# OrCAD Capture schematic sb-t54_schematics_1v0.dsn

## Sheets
1 01. Board info: title: SB-T54    01. Board info; note: 8000040000
2 02. CoM Connector: size C; title: SB-T54    02. CARRIER BOARD INTERFACE
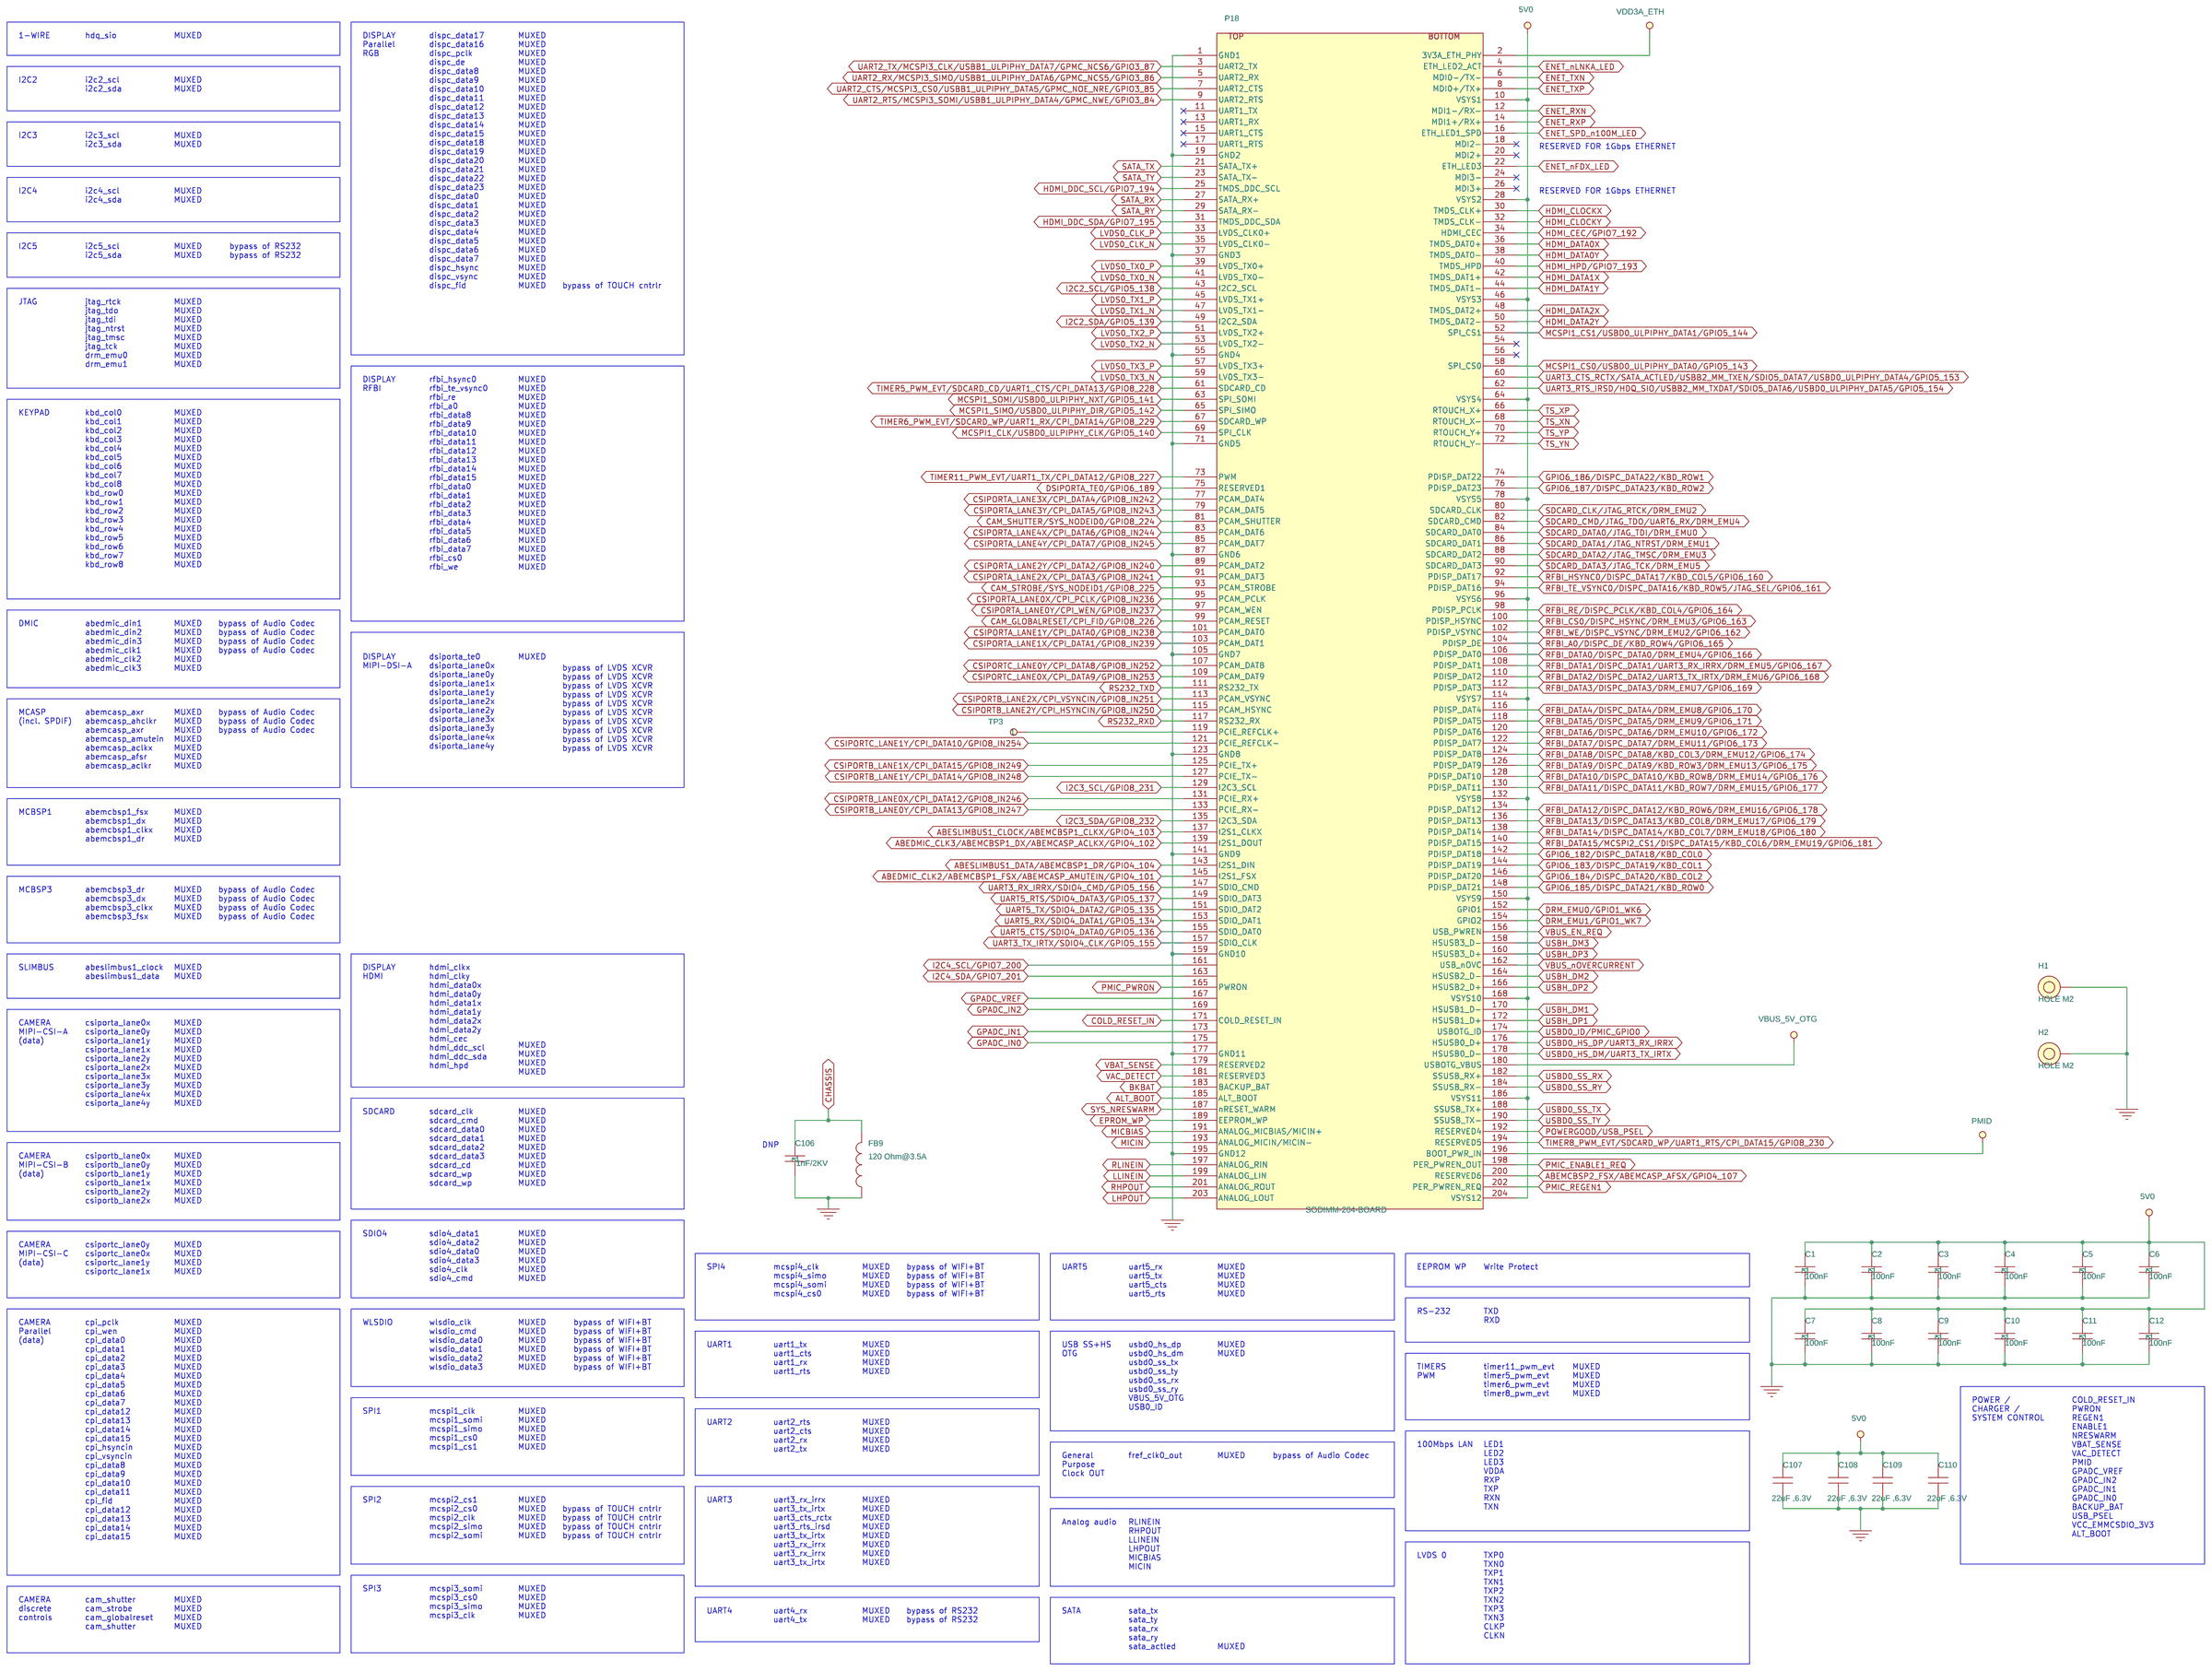
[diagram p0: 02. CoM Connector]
3 03. DVI Transmitter: size B; title: SB-T54  03. DVI Transmitter; rev: 1.0
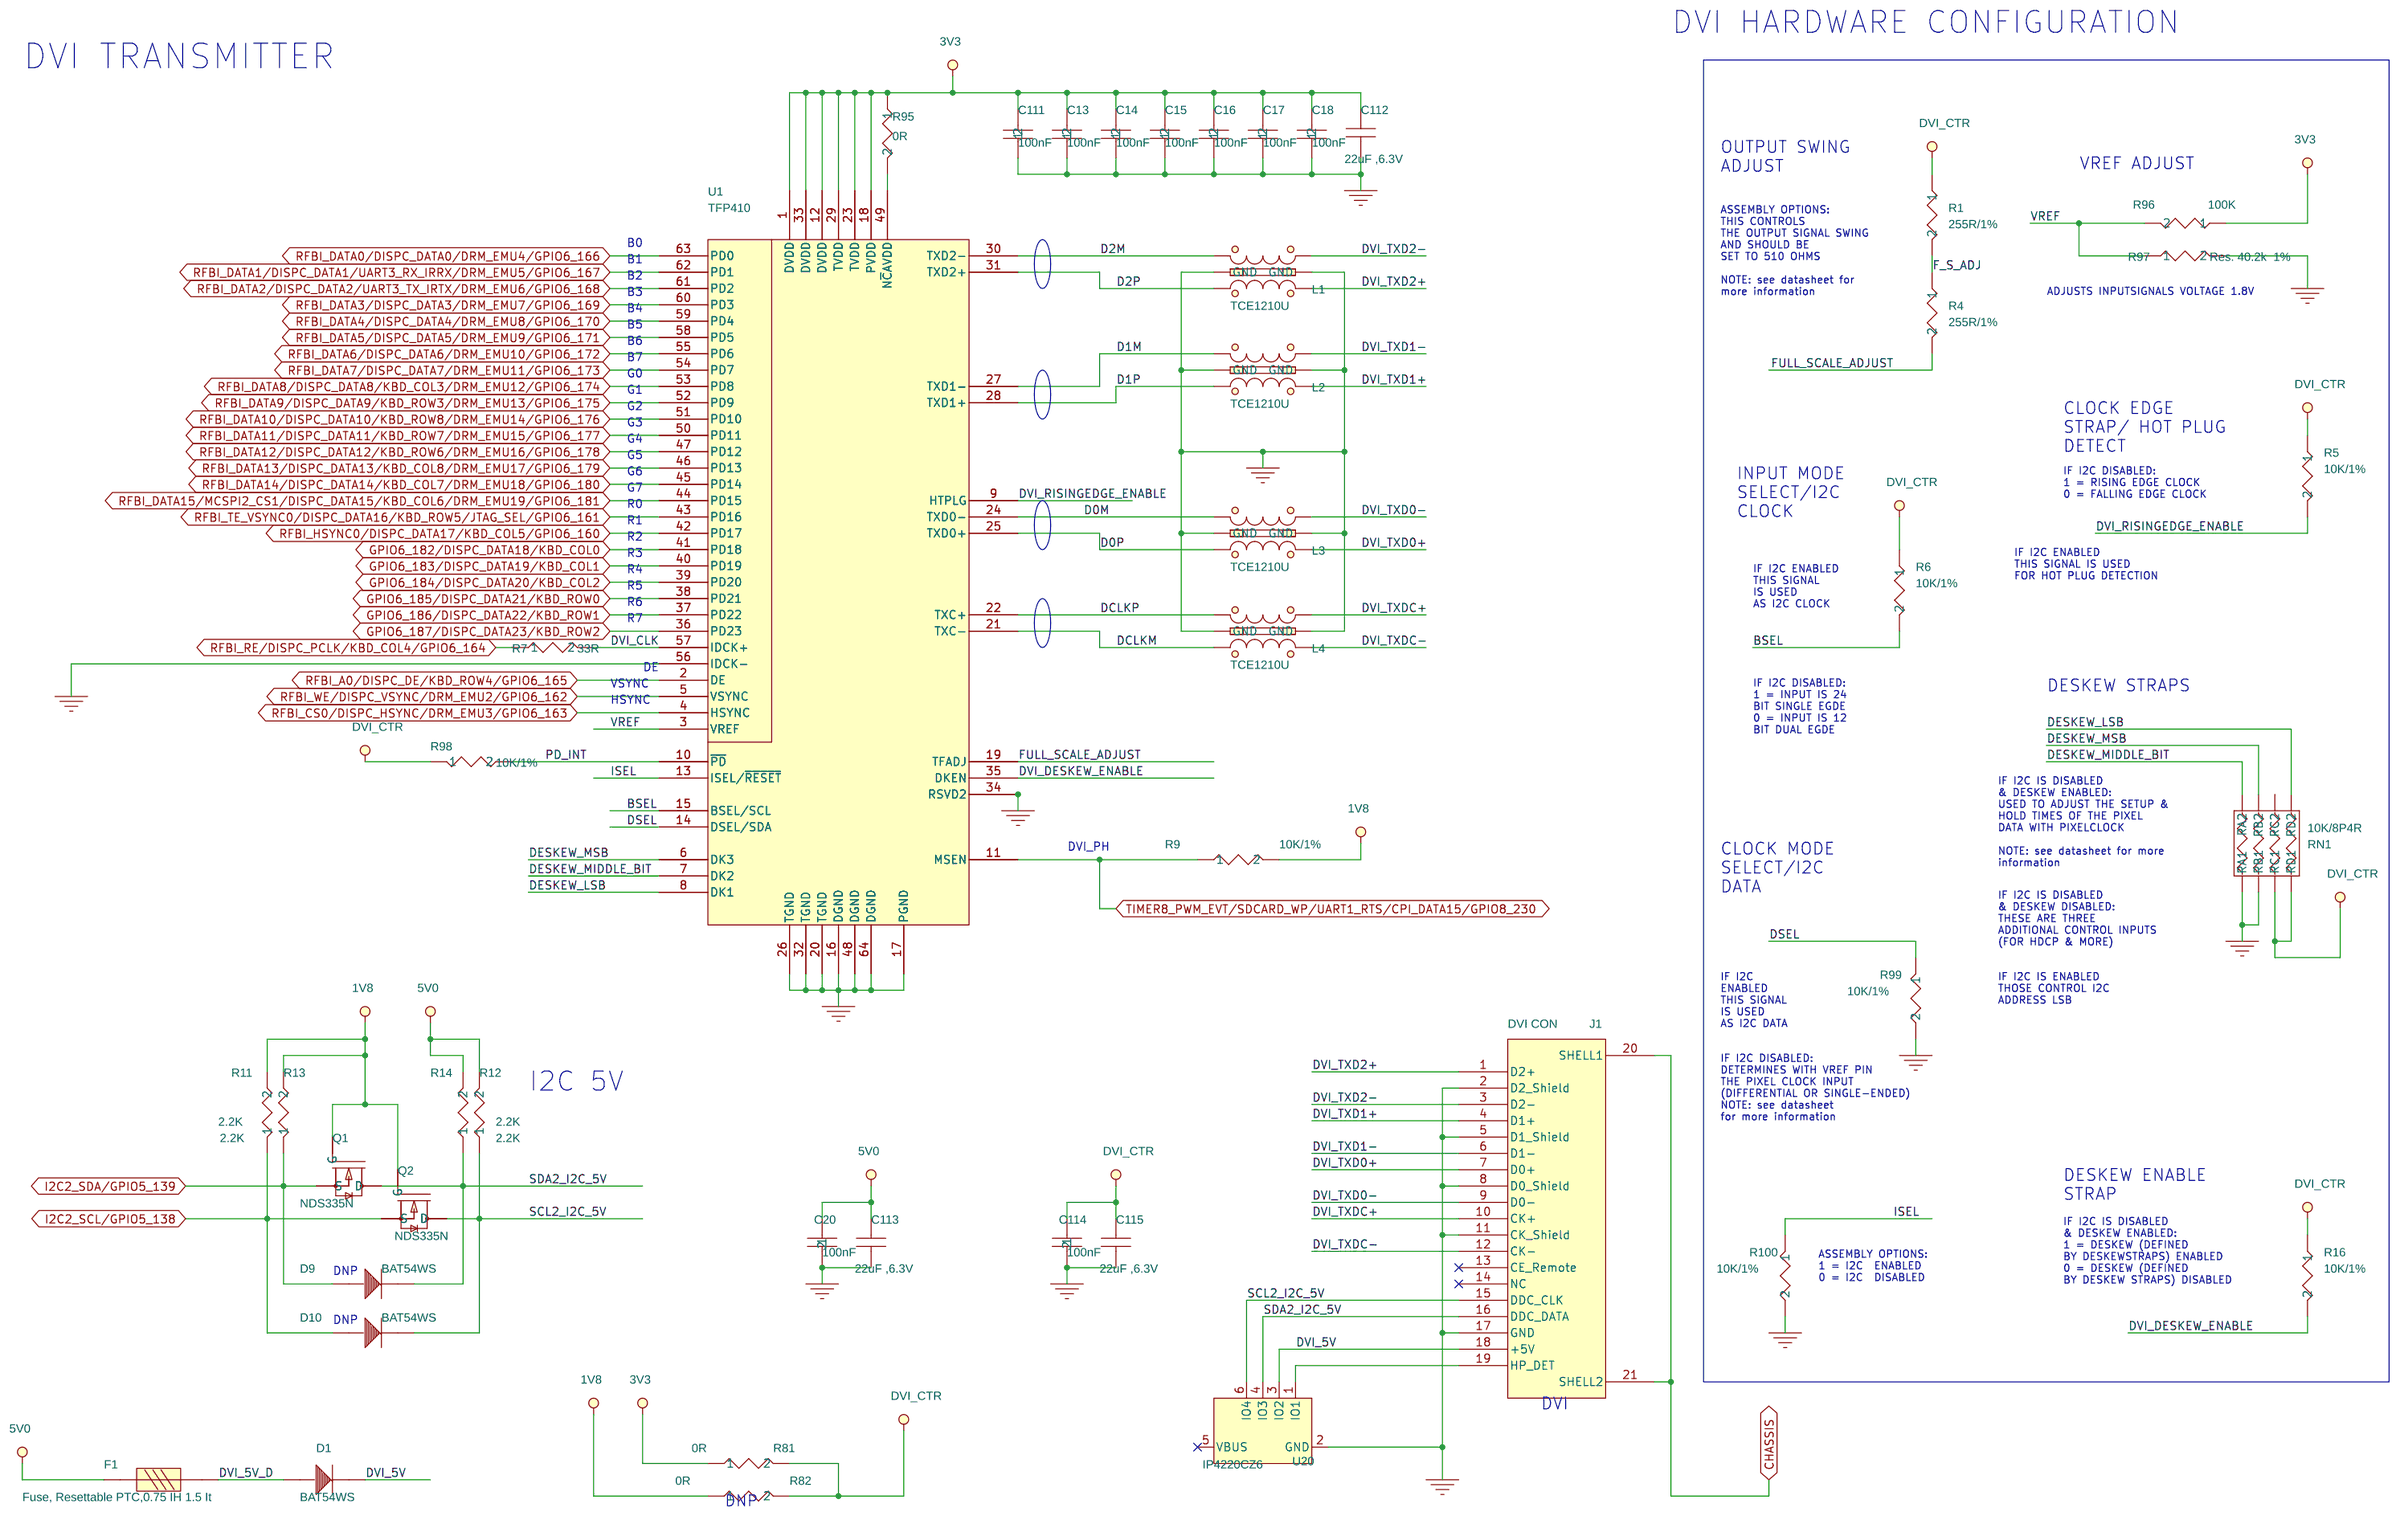
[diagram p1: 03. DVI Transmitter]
4 04. Parallel RGB: size B; title: SB-54  04. Parallel RGB; rev: 1.0
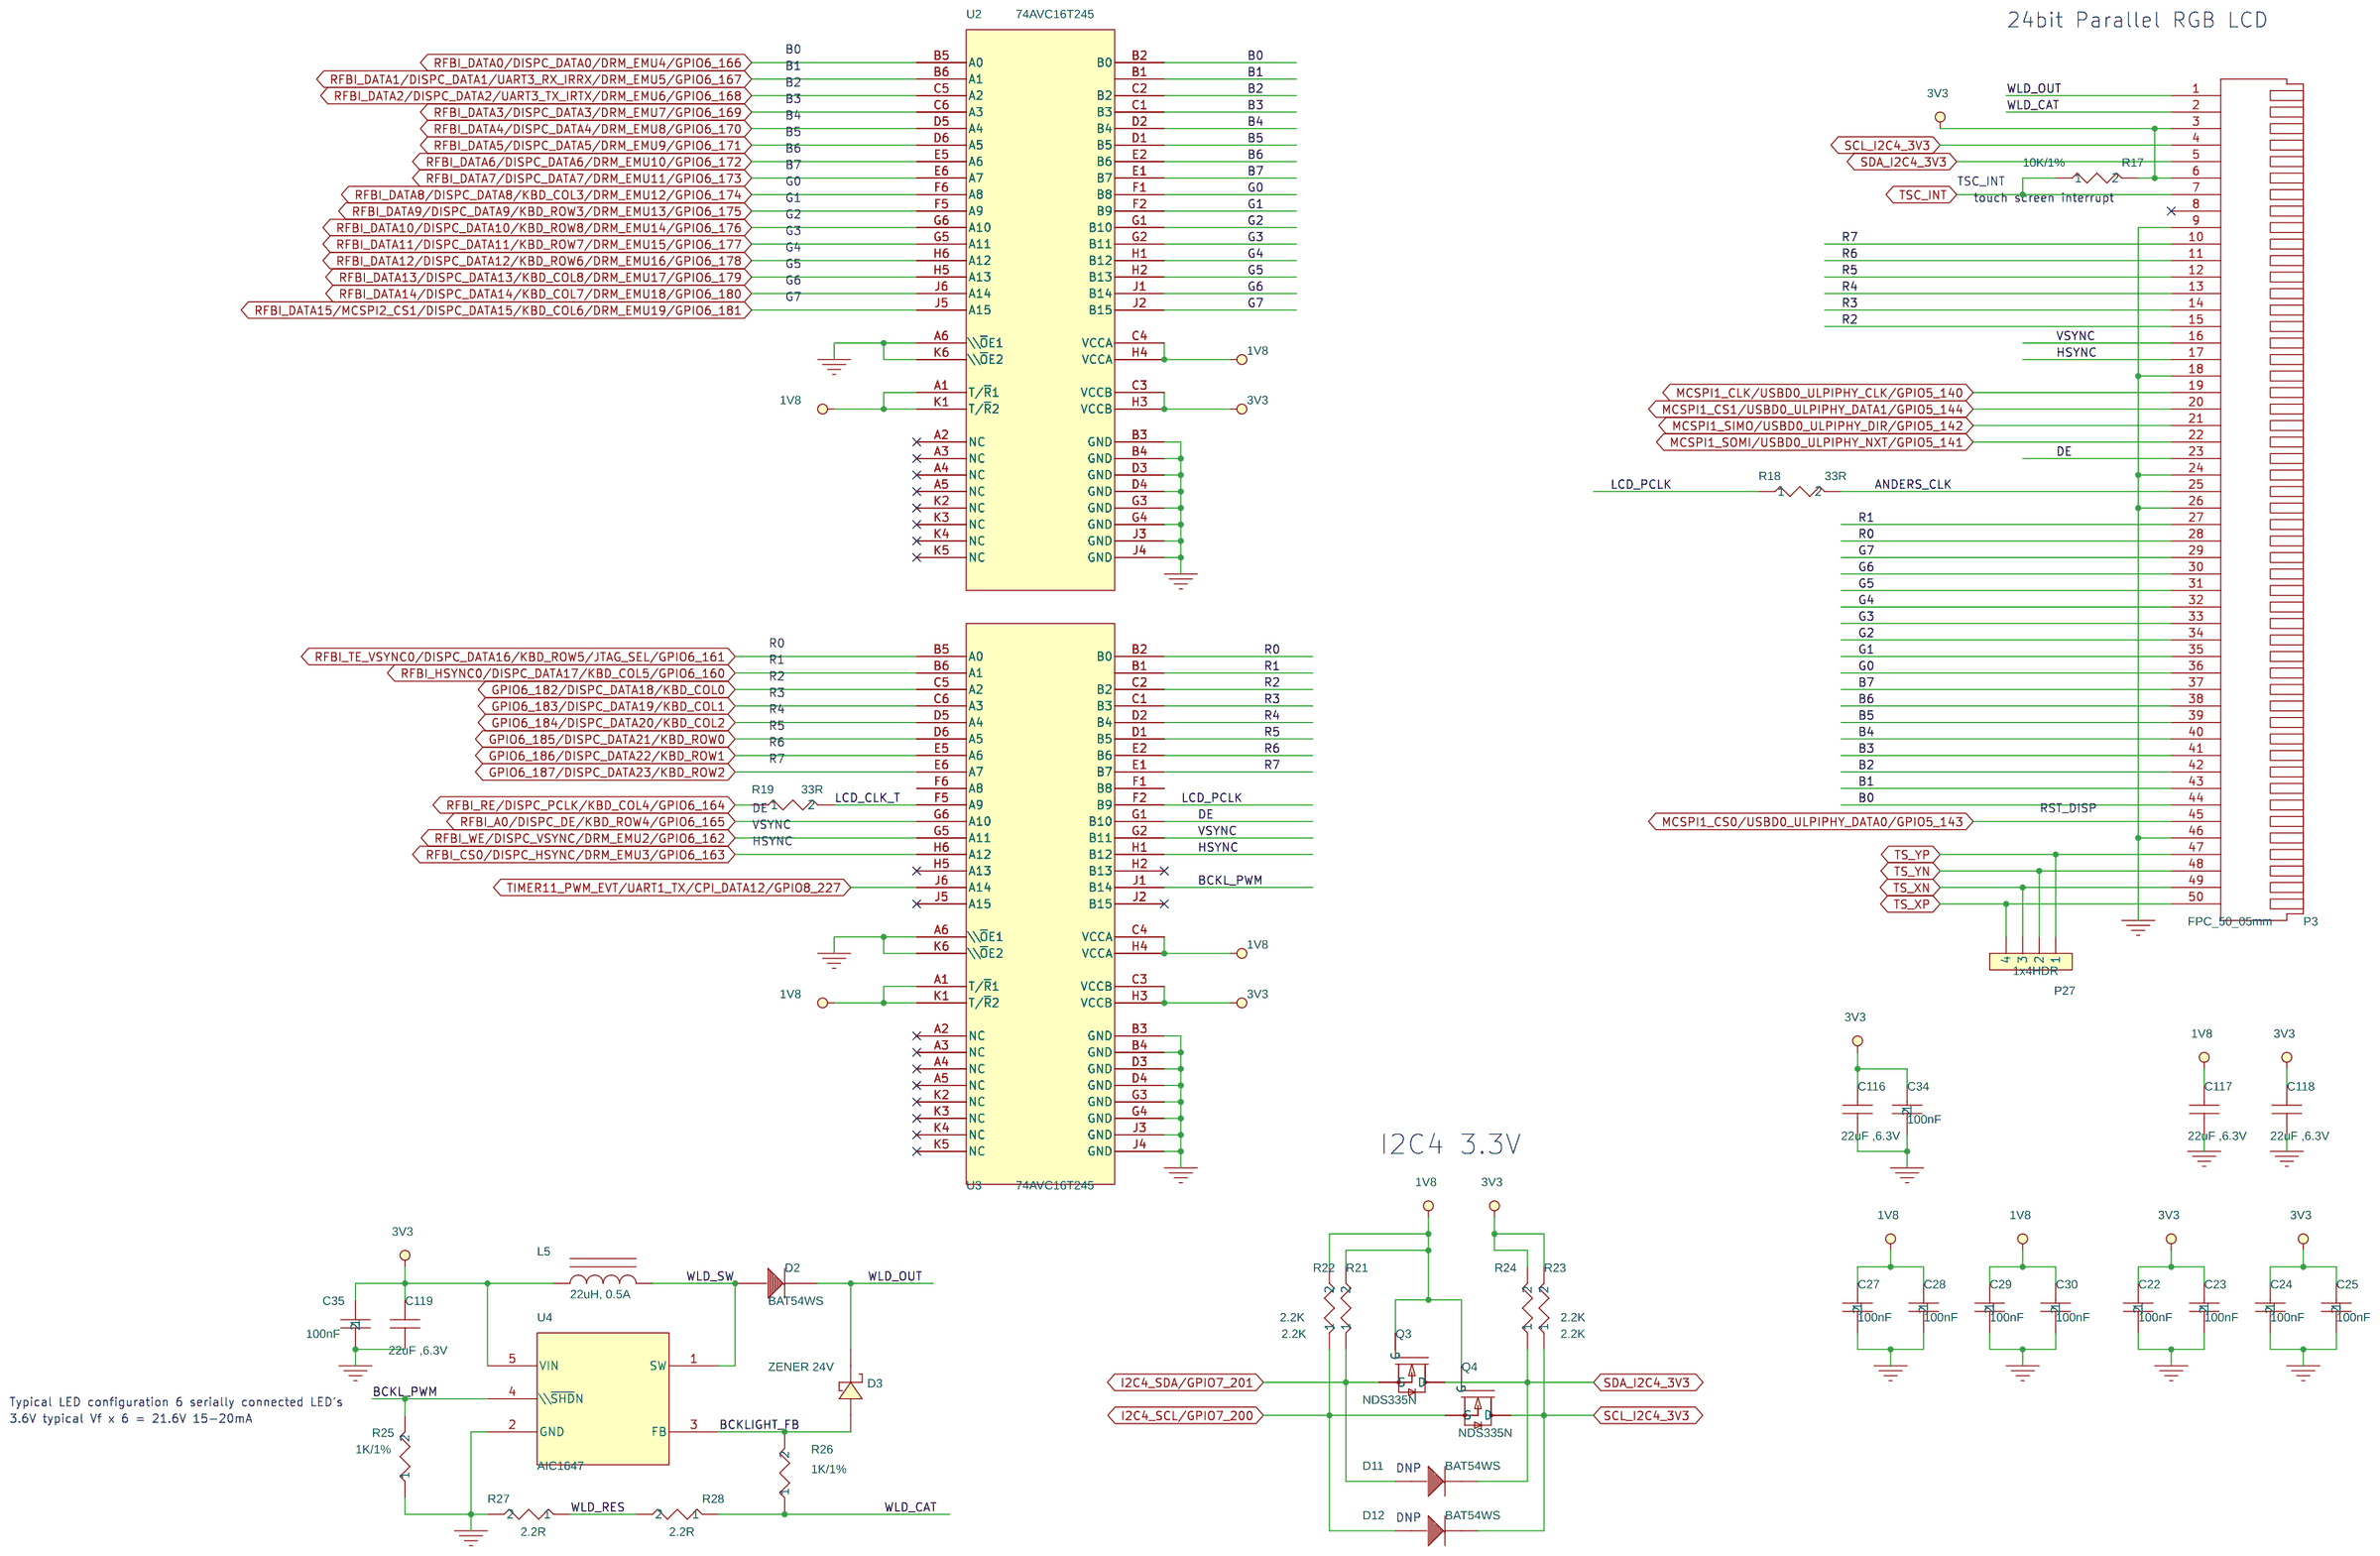
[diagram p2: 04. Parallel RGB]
5 06. MMC & UARTS: size B; title: SB-T54  06. MMC & UARTS; rev: 1.0
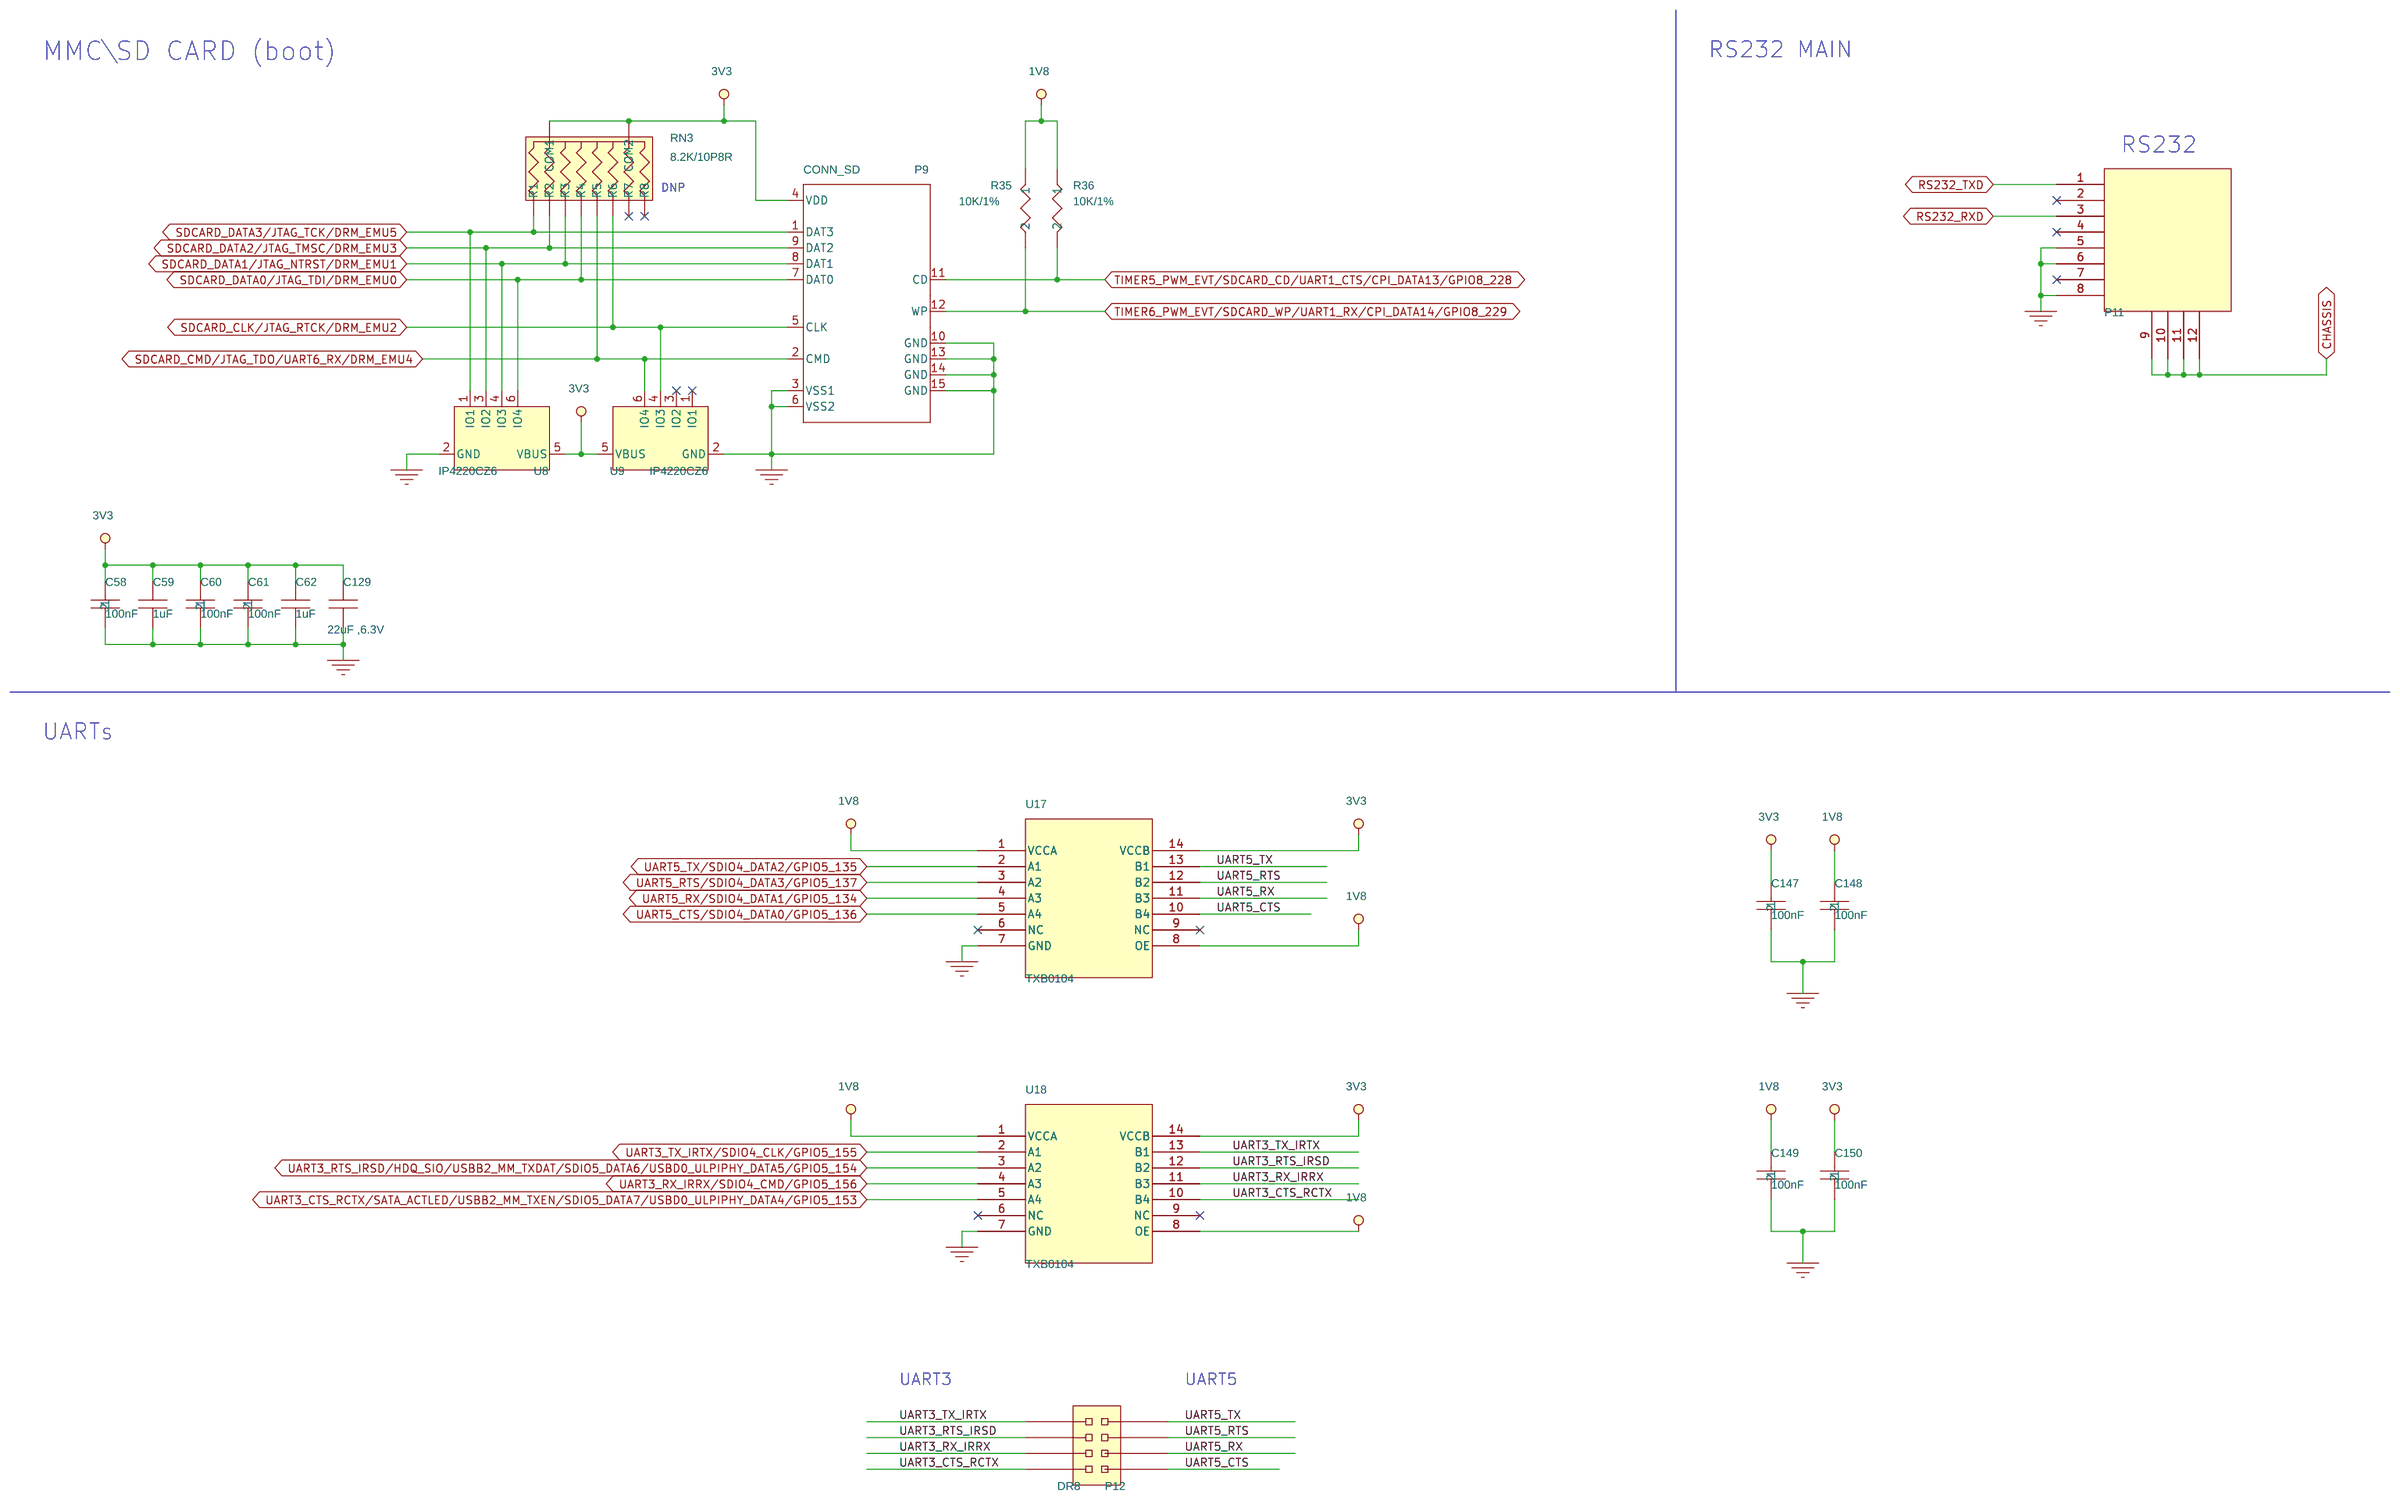
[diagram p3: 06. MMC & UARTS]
6 08. SETUP: size B; title: SB-T54    08. SETUP; rev: 1.0
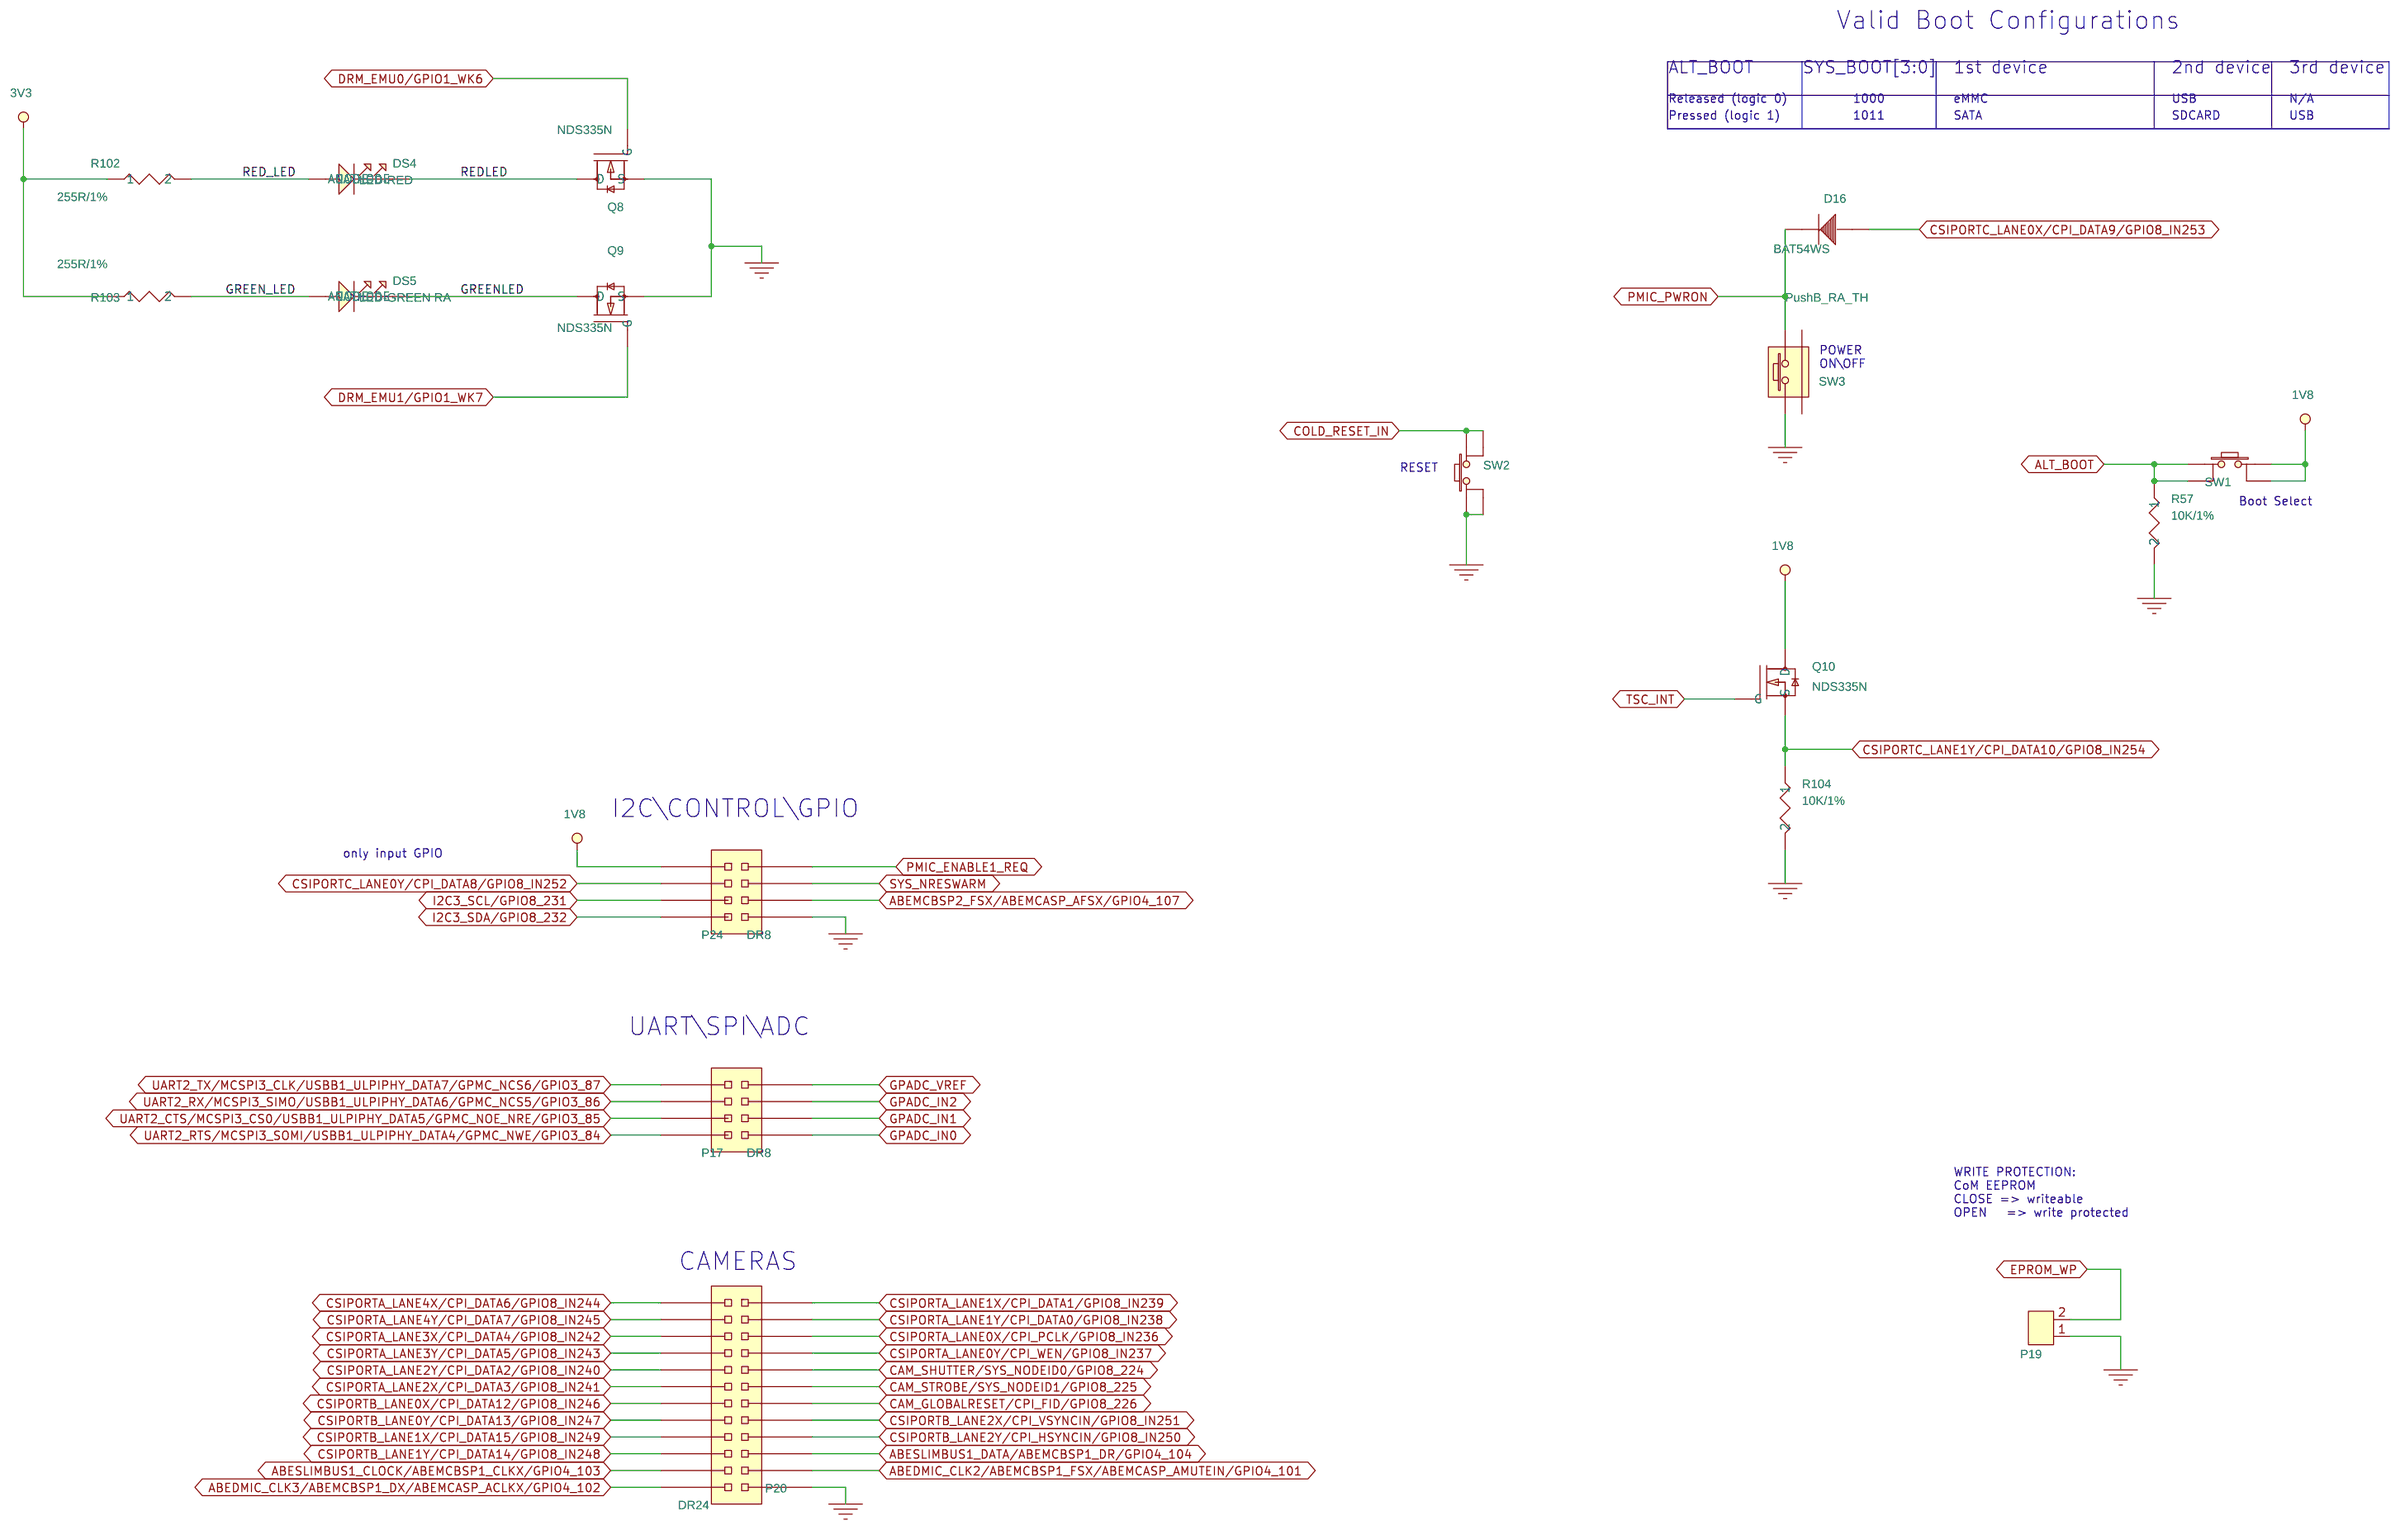
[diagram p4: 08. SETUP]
7 09. POWER: size B; title: SB-T54    09. POWER; rev: 1.0
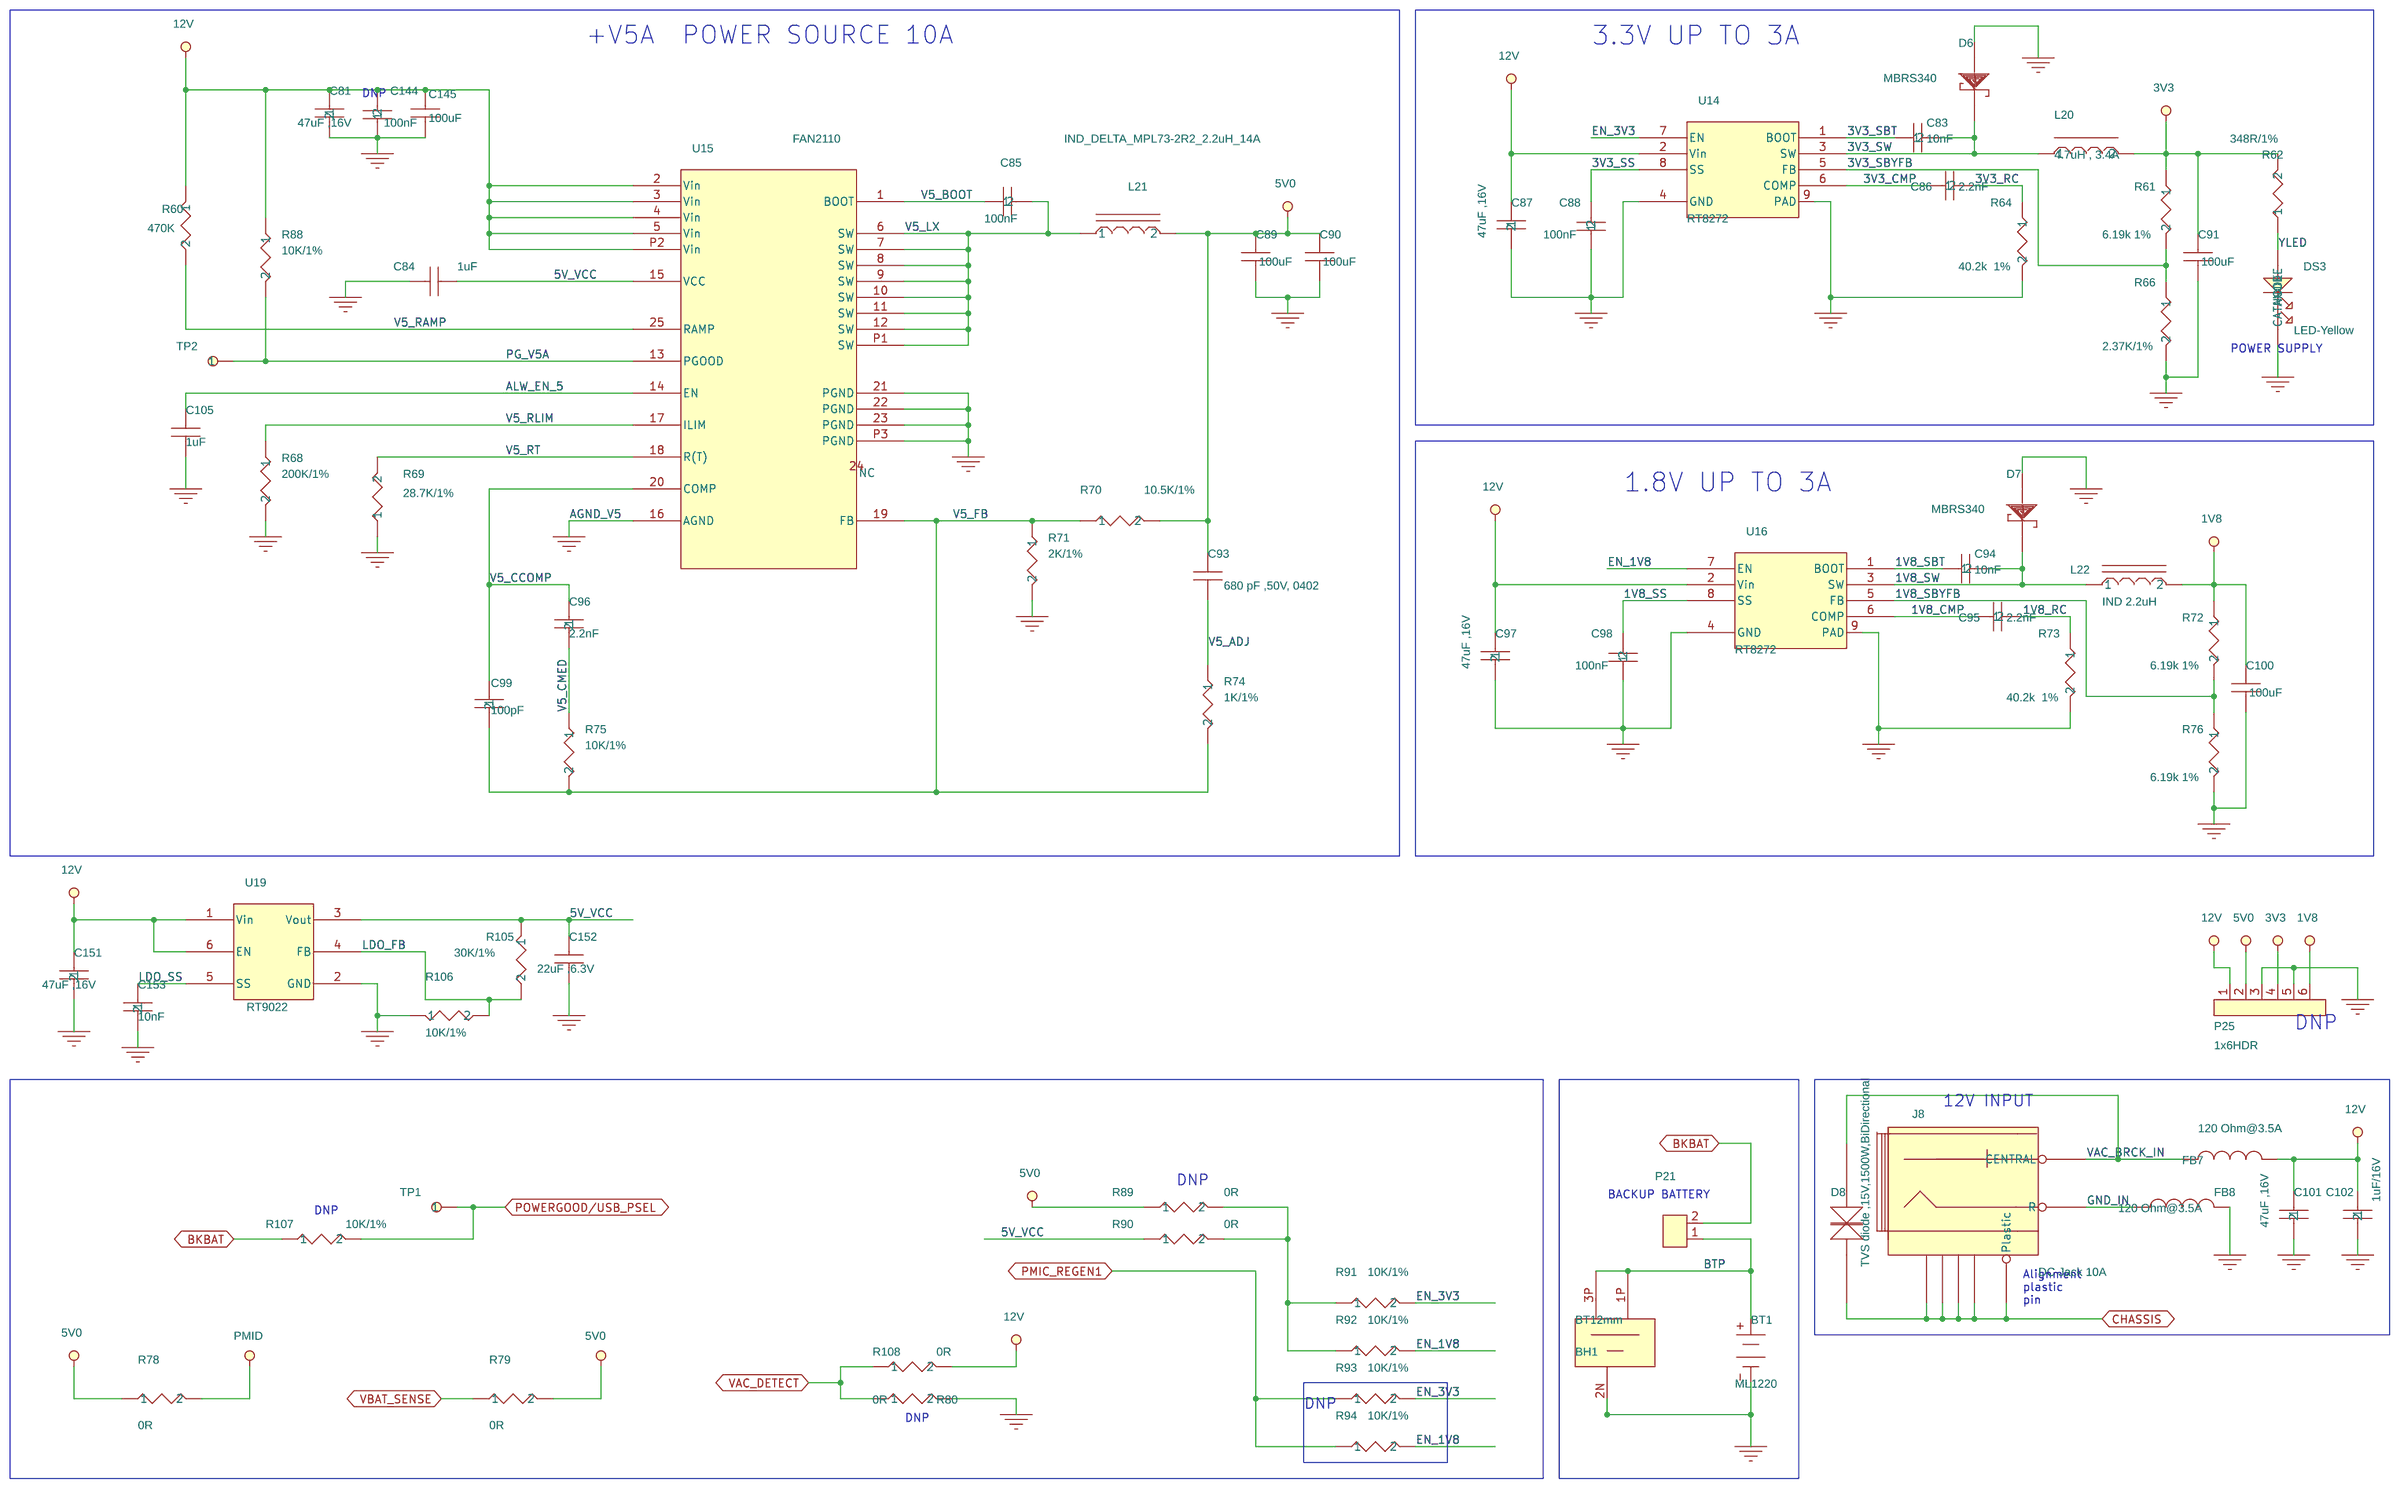
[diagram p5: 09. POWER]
8 07. ETH\USB\AUDIO: size B; title: SB-T54    07. ETH\USB\AUDIO; rev: 1.0
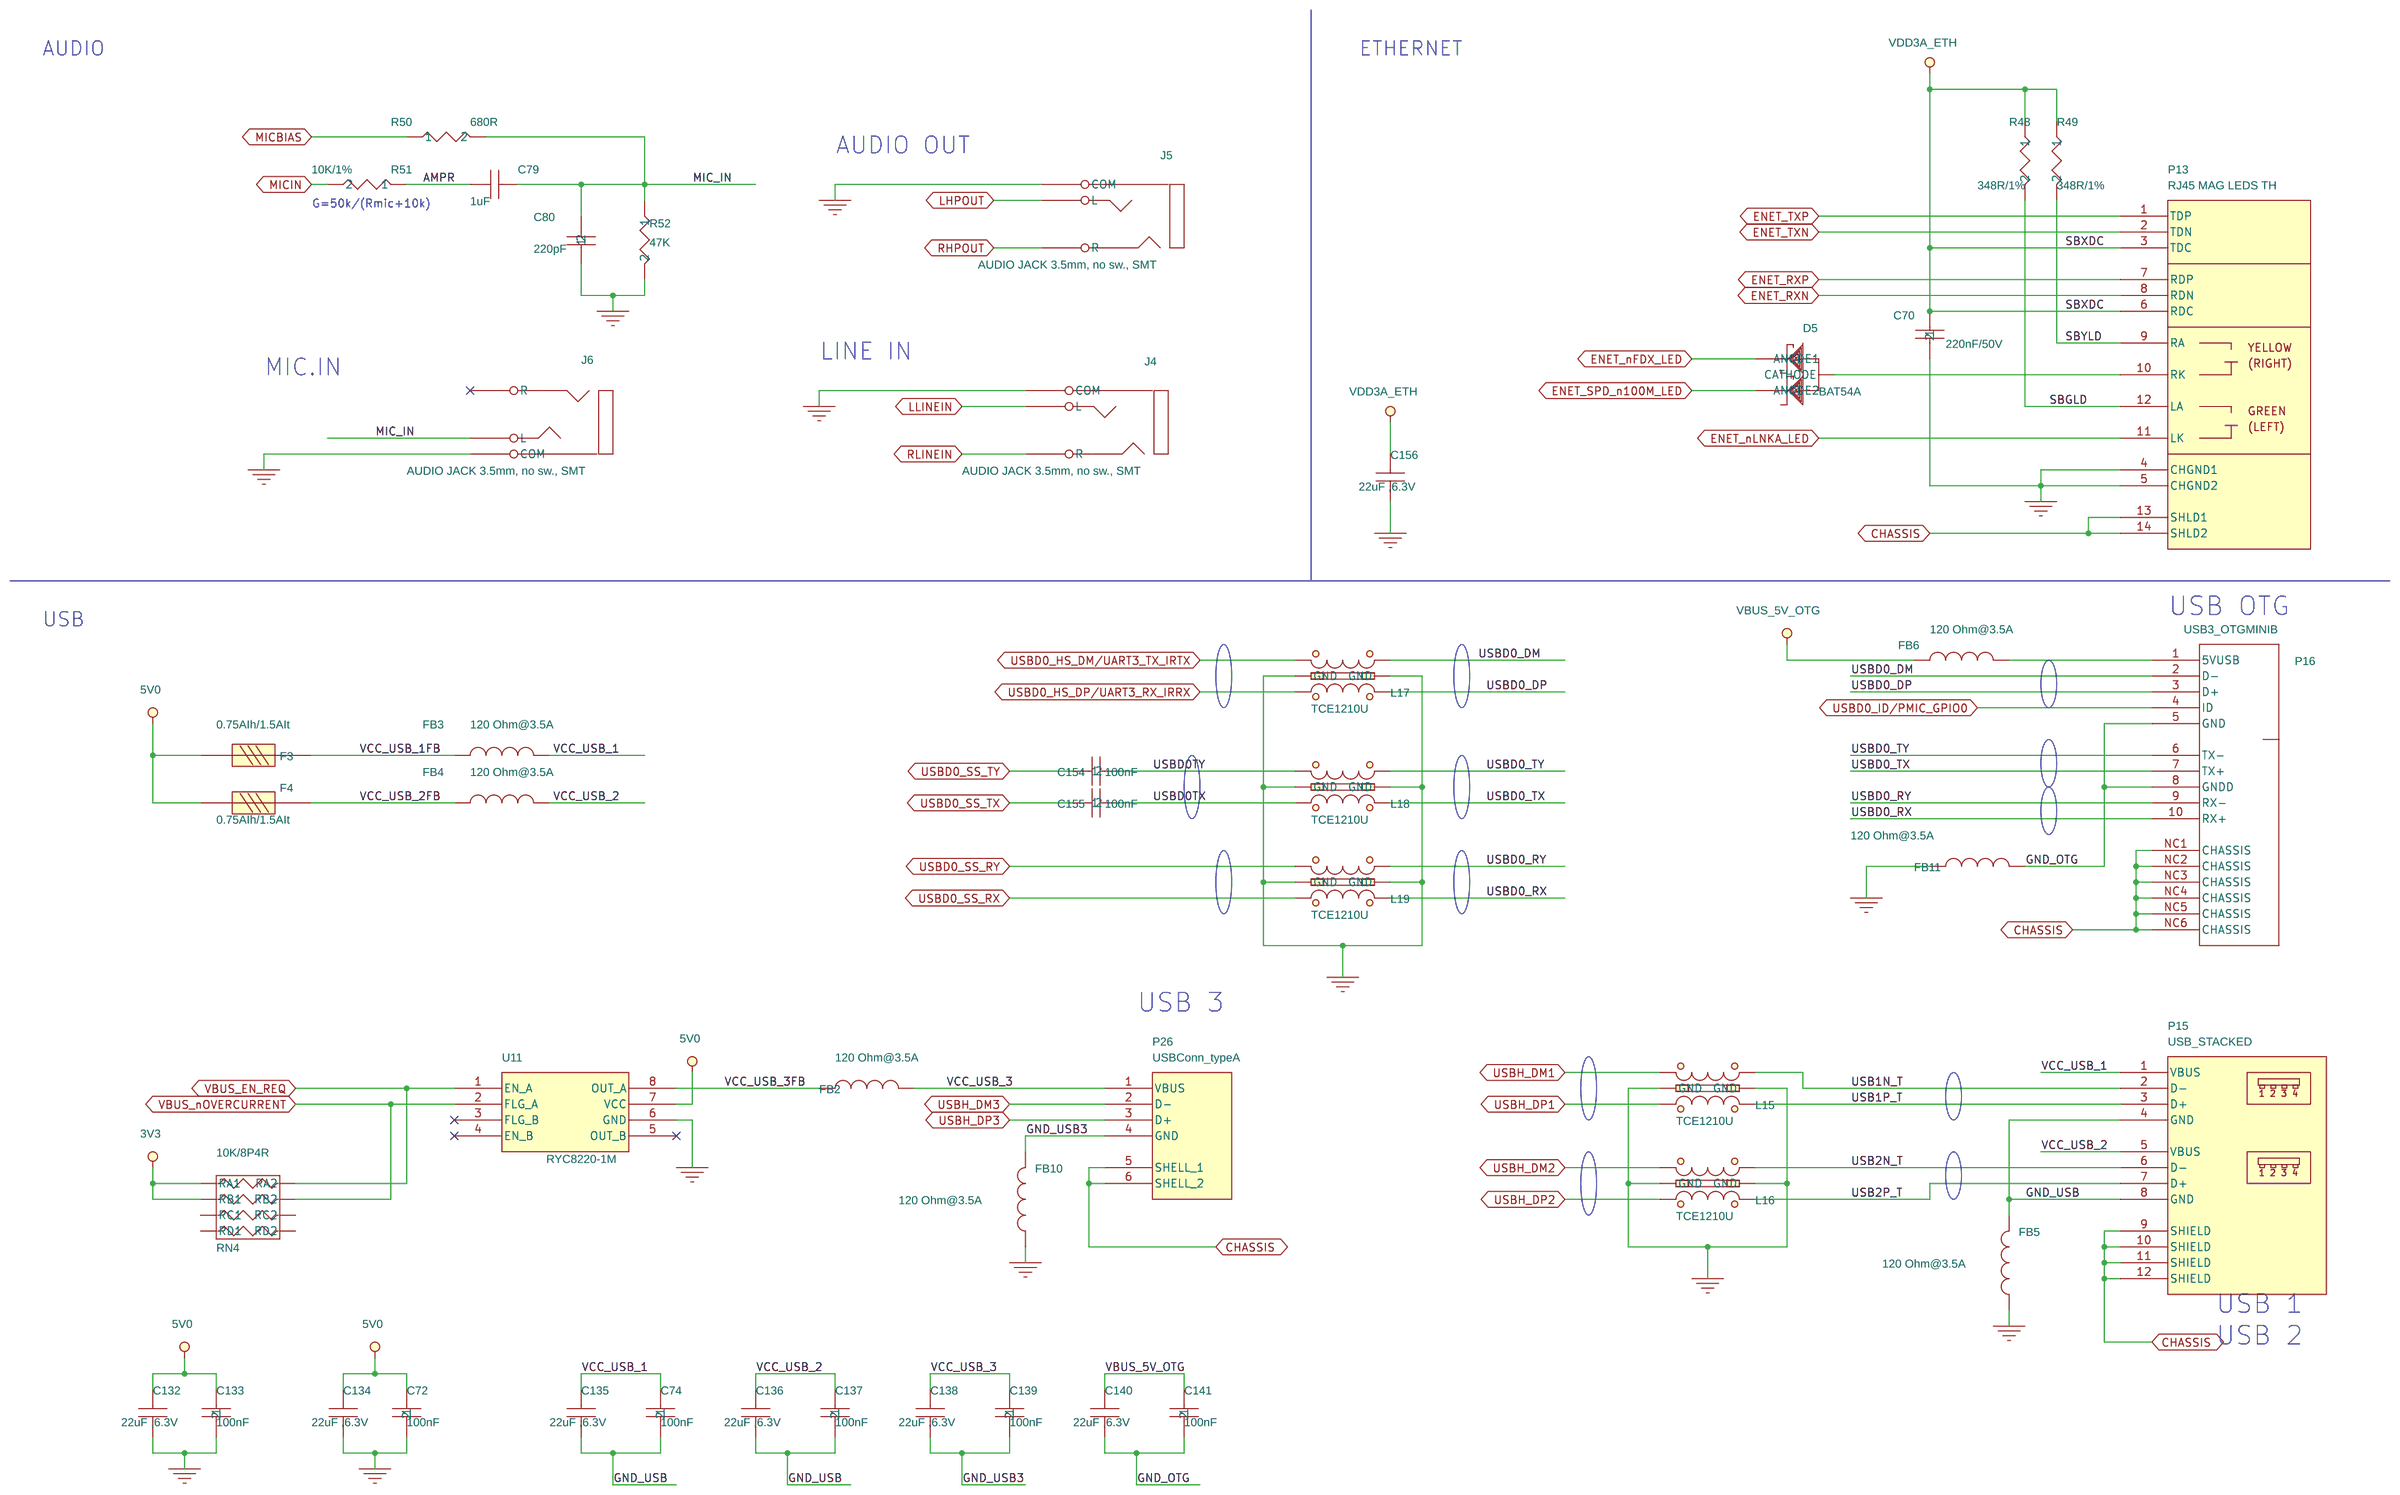
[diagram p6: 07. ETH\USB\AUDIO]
9 05. VIDEO\SATA\EEPROM: size B; title: SB-T45   05. VIDEO\SATA\EEPROM; rev: 1.0
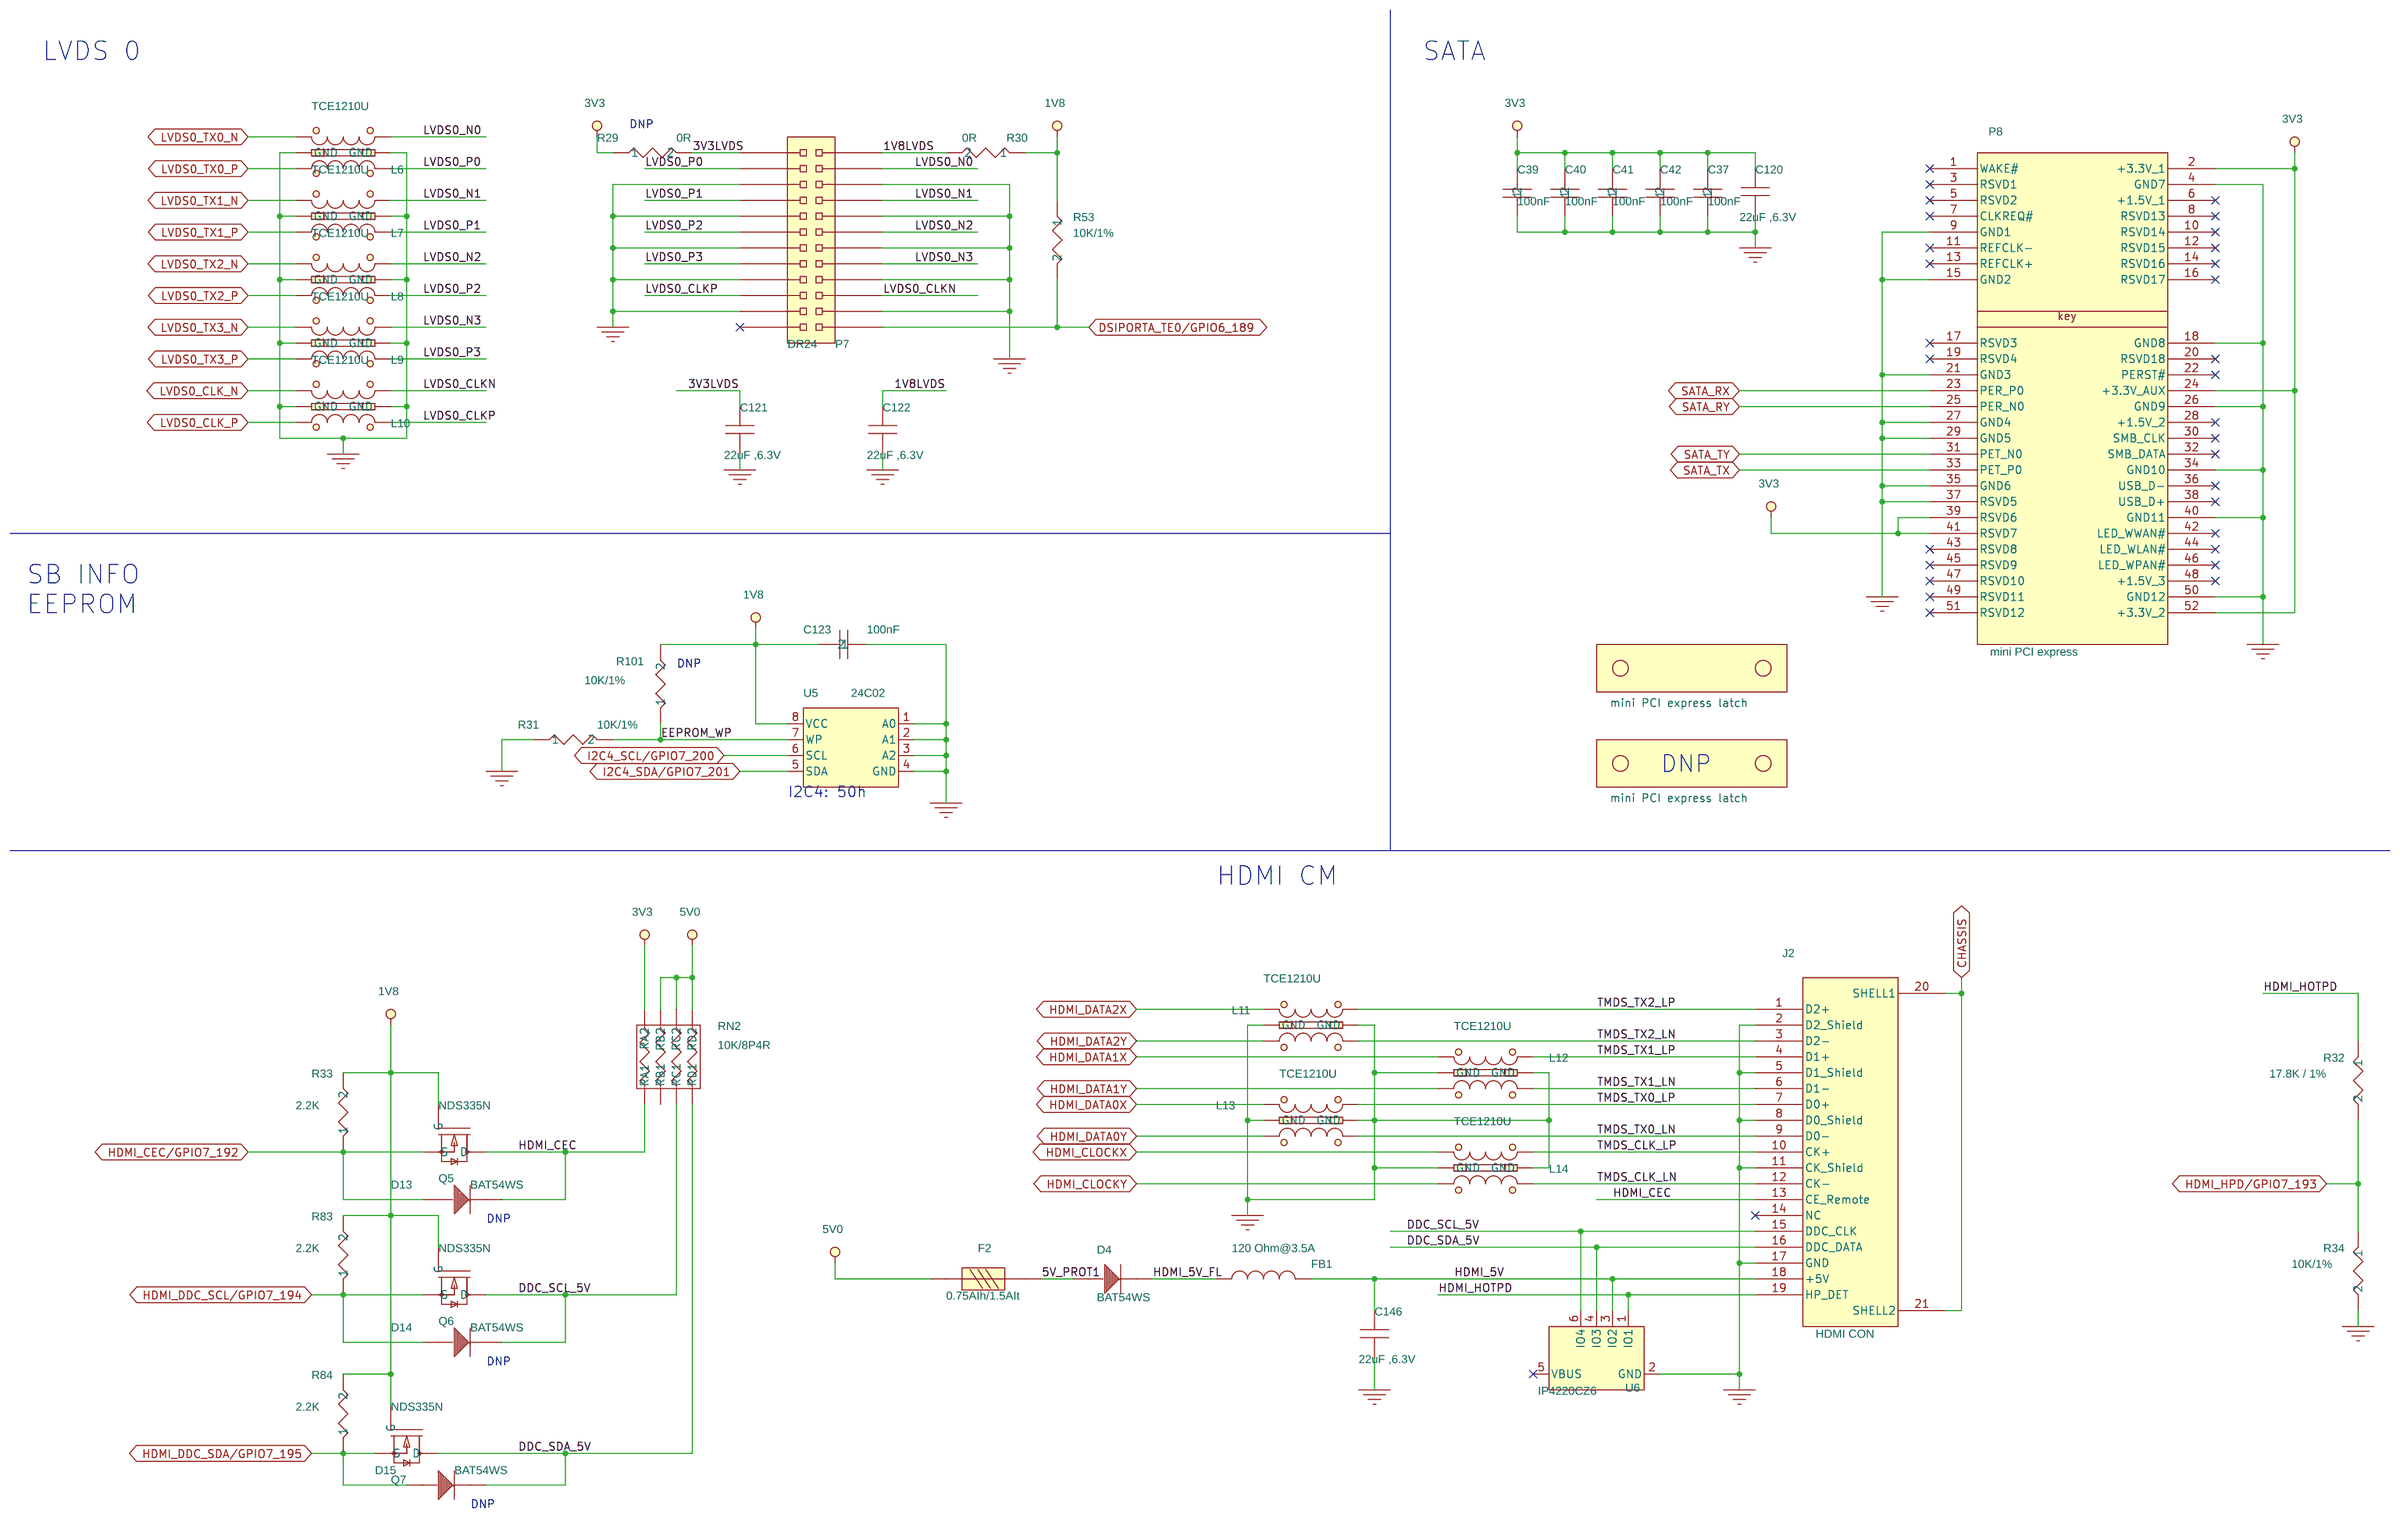
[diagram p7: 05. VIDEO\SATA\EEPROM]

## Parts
sheet 02. CoM Connector
C1  100nF  [RC0402]
C2  100nF  [RC0402]
C3  100nF  [RC0402]
C4  100nF  [RC0402]
C5  100nF  [RC0402]
C6  100nF  [RC0402]
C7  100nF  [RC0402]
C8  100nF  [RC0402]
C9  100nF  [RC0402]
C10  100nF  [RC0402]
C11  100nF  [RC0402]
C12  100nF  [RC0402]
C106  1nF/2KV  [C1812]
C107  22uF ,6.3V  [RC0603]
C108  22uF ,6.3V  [RC0603]
C109  22uF ,6.3V  [RC0603]
C110  22uF ,6.3V  [RC0603]
FB9  120 Ohm@3.5A  [1206]
H1  HOLE M2  [M2PAD]
H2  HOLE M2  [M2PAD]
P18  SODIMM-204-BOARD  [190I20400S]
TP3  TESTPOINT  [TP1x1]
sheet 03. DVI Transmitter
C13  100nF  [RC0402]
C14  100nF  [RC0402]
C15  100nF  [RC0402]
C16  100nF  [RC0402]
C17  100nF  [RC0402]
C18  100nF  [RC0402]
C20  100nF  [RC0402]
C111  100nF  [RC0402]
C112  22uF ,6.3V  [RC0603]
C113  22uF ,6.3V  [RC0603]
C114  100nF  [RC0402]
C115  22uF ,6.3V  [RC0603]
D1  BAT54WS  [SOD-323]
D9  BAT54WS  [SOD-323]
D10  BAT54WS  [SOD-323]
F1  Fuse, Resettable PTC,0.75 IH 1.5 It  [FUSE-1206]
J1  DVI CON  [HDMI-A19-RASM]
L1  TCE1210U  [EMI1012-ESD]
L2  TCE1210U  [EMI1012-ESD]
L3  TCE1210U  [EMI1012-ESD]
L4  TCE1210U  [EMI1012-ESD]
Q1  NDS335N  [SOT23]
Q2  NDS335N  [SOT23]
R1  255R/1%  [RC0402]
R4  255R/1%  [RC0402]
R5  10K/1%  [RC0402]
R6  10K/1%  [RC0402]
R7  33R  [RC0402]
R9  10K/1%  [RC0402]
R11  2.2K  [RC0402]
R12  2.2K  [RC0402]
R13  2.2K  [RC0402]
R14  2.2K  [RC0402]
R16  10K/1%  [RC0402]
R81  0R  [RC0402]
R82  0R  [RC0402]
R95  0R  [RC0402]
R96  100K  [RC0402]
R97  Res. 40.2k  1%  [0402]
R98  10K/1%  [RC0402]
R99  10K/1%  [RC0402]
R100  10K/1%  [RC0402]
RN1  10K/8P4R  [RESNET8P0805]
U1  TFP410  [TQFP-64]
U20  IP4220CZ6  [SOT23-6L]
sheet 04. Parallel RGB
C22  100nF  [RC0402]
C23  100nF  [RC0402]
C24  100nF  [RC0402]
C25  100nF  [RC0402]
C27  100nF  [RC0402]
C28  100nF  [RC0402]
C29  100nF  [RC0402]
C30  100nF  [RC0402]
C34  100nF  [RC0402]
C35  100nF  [RC0402]
C116  22uF ,6.3V  [RC0603]
C117  22uF ,6.3V  [RC0603]
C118  22uF ,6.3V  [RC0603]
C119  22uF ,6.3V  [RC0603]
D2  BAT54WS  [SOD-323]
D3  ZENER 24V  [SOD-123]
D11  BAT54WS  [SOD-323]
D12  BAT54WS  [SOD-323]
L5  22uH, 0.5A  [IND4x4_5x3_2S]
P3  FPC_50_05mm  [FPC05SM50-1]
P27  1x4HDR  [1X4THHDR]
Q3  NDS335N  [SOT23]
Q4  NDS335N  [SOT23]
R17  10K/1%  [RC0402]
R18  33R  [RC0402]
R19  33R  [RC0402]
R21  2.2K  [RC0402]
R22  2.2K  [RC0402]
R23  2.2K  [RC0402]
R24  2.2K  [RC0402]
R25  1K/1%  [RC0402]
R26  1K/1%  [RC0402]
R27  2.2R  [RC0402]
R28  2.2R  [RC0402]
U2  74AVC16T245  [BGA-56-065-7X4_5]
U3  74AVC16T245  [BGA-56-065-7X4_5]
U4  AIC1647  [SOT23-5]
sheet 05. VIDEO\SATA\EEPROM
C37  100nF  [RC0402]
C39  100nF  [RC0402]
C40  100nF  [RC0402]
C41  100nF  [RC0402]
C42  100nF  [RC0402]
C120  22uF ,6.3V  [RC0603]
C121  22uF ,6.3V  [RC0603]
C122  22uF ,6.3V  [RC0603]
C123  100nF  [RC0402]
C146  22uF ,6.3V  [RC0603]
D4  BAT54WS  [SOD-323]
D13  BAT54WS  [SOD-323]
D14  BAT54WS  [SOD-323]
D15  BAT54WS  [SOD-323]
F2  0.75AIh/1.5AIt  [FUSE-1206]
FB1  120 Ohm@3.5A  [1206]
J2  HDMI CON  [HDMI-A19-RASM]
L6  TCE1210U  [EMI1012-ESD]
L7  TCE1210U  [EMI1012-ESD]
L8  TCE1210U  [EMI1012-ESD]
L9  TCE1210U  [EMI1012-ESD]
L10  TCE1210U  [EMI1012-ESD]
L11  TCE1210U  [EMI1012-ESD]
L12  TCE1210U  [EMI1012-ESD]
L13  TCE1210U  [EMI1012-ESD]
L14  TCE1210U  [EMI1012-ESD]
P7  DR24  [2X12THHDR]
P8  mini PCI express  [MINIPCIE-4]
P22  mini PCI express latch  [MINIPCIE-4]
P23  mini PCI express latch  [MINIPCIE-4]
Q5  NDS335N  [SOT23]
Q6  NDS335N  [SOT23]
Q7  NDS335N  [SOT23]
R29  0R  [RC0402]
R30  0R  [RC0402]
R31  10K/1%  [RC0402]
R32  17.8K / 1%  [RC0402]
R33  2.2K  [RC0402]
R34  10K/1%  [RC0402]
R53  10K/1%  [RC0402]
R83  2.2K  [RC0402]
R84  2.2K  [RC0402]
R101  10K/1%  [RC0402]
RN2  10K/8P4R  [RESNET8P0805]
U5  24C02  [MO-229VCED-2]
U6  IP4220CZ6  [SOT23-6L]
sheet 06. MMC & UARTS
C58  100nF  [RC0402]
C59  1uF  [RC0402]
C60  100nF  [RC0402]
C61  100nF  [RC0402]
C62  1uF  [RC0402]
C129  22uF ,6.3V  [RC0603]
C147  100nF  [RC0402]
C148  100nF  [RC0402]
C149  100nF  [RC0402]
C150  100nF  [RC0402]
P9  CONN_SD  [SD-RA-SM]
P11  Ultra Mini Serial Connector  [UMS-8]
P12  DR8  [2X4SMHDR]
R35  10K/1%  [RC0402]
R36  10K/1%  [RC0402]
RN3  8.2K/10P8R  [RESNET10P1206]
U8  IP4220CZ6  [SOT23-6L]
U9  IP4220CZ6  [SOT23-6L]
U17  TXB0104  [TSSOP-14]
U18  TXB0104  [TSSOP-14]
sheet 07. ETH\USB\AUDIO
C70  220nF/50V  [C0805]
C72  100nF  [RC0402]
C74  100nF  [RC0402]
C79  1uF  [RC0402]
C80  220pF  [RC0603]
C132  22uF ,6.3V  [RC0603]
C133  100nF  [RC0402]
C134  22uF ,6.3V  [RC0603]
C135  22uF ,6.3V  [RC0603]
C136  22uF ,6.3V  [RC0603]
C137  100nF  [RC0402]
C138  22uF ,6.3V  [RC0603]
C139  100nF  [RC0402]
C140  22uF ,6.3V  [RC0603]
C141  100nF  [RC0402]
C154  100nF  [RC0402]
C155  100nF  [RC0402]
C156  22uF ,6.3V  [RC0603]
D5  BAT54A  [SOT23]
F3  0.75AIh/1.5AIt  [FUSE-1206]
F4  0.75AIh/1.5AIt  [FUSE-1206]
FB2  120 Ohm@3.5A  [1206]
FB3  120 Ohm@3.5A  [1206]
FB4  120 Ohm@3.5A  [1206]
FB5  120 Ohm@3.5A  [1206]
FB6  120 Ohm@3.5A  [1206]
FB10  120 Ohm@3.5A  [1206]
FB11  120 Ohm@3.5A  [1206]
J4  AUDIO JACK 3.5mm, no sw., SMT  [AJ35-3P-SM]
J5  AUDIO JACK 3.5mm, no sw., SMT  [AJ35-3P-SM]
J6  AUDIO JACK 3.5mm, no sw., SMT  [AJ35-3P-SM]
L15  TCE1210U  [EMI1012-ESD]
L16  TCE1210U  [EMI1012-ESD]
L17  TCE1210U  [EMI1012-ESD]
L18  TCE1210U  [EMI1012-ESD]
L19  TCE1210U  [EMI1012-ESD]
P13  RJ45 MAG LEDS TH  [RJETH-LED-TH]
P15  USB_STACKED  [USB-2XA-TH]
P16  USB3_OTGMINIB  [MICRO-USB3-AB-RA-SM]
P26  USBConn_typeA  [USB-A-SM]
R48  348R/1%  [RC0402]
R49  348R/1%  [RC0402]
R50  680R  [RC0402]
R51  10K/1%  [RC0402]
R52  47K  [RC0402]
RN4  10K/8P4R  [RESNET8P0805]
U11  RYC8220-1M  [SO-8-150]
sheet 08. SETUP
D16  BAT54WS  [SOD-323]
DS4  LED-RED  [LED-1206]
DS5  LED-GREEN RA  [LED3x1RASM]
P17  DR8  [2X4SMHDR]
P19  HDR1X2  [1X2THHDR]
P20  DR24  [2X12THHDR]
P24  DR8  [2X4SMHDR]
Q8  NDS335N  [SOT23]
Q9  NDS335N  [SOT23]
Q10  NDS335N  [SOT23]
R57  10K/1%  [RC0402]
R102  255R/1%  [RC0402]
R103  255R/1%  [RC0402]
R104  10K/1%  [RC0402]
SW1  PushB  [TACTSW6x6SM]
SW2  PushB  [TACTSW6x6SM]
SW3  PushB_RA_TH  [TACTSW6x6THRA]
sheet 09. POWER
BH1  BT12mm  [BattH12mm-SM]
BT1  ML1220  [BT1220SM]
C81  47uF ,16V  [C1210H2_5]
C83  10nF  [RC0402]
C84  1uF  [RC0402]
C85  100nF  [RC0402]
C86  2.2nF  [RC0402]
C87  47uF ,16V  [C1210H2_5]
C88  100nF  [RC0402]
C89  100uF  [C1206]
C90  100uF  [C1206]
C91  100uF  [C1206]
C93  680 pF ,50V, 0402  [0402]
C94  10nF  [RC0402]
C95  2.2nF  [RC0402]
C96  2.2nF  [RC0402]
C97  47uF ,16V  [C1210H2_5]
C98  100nF  [RC0402]
C99  100pF  [RC0402]
C100  100uF  [C1206]
C101  47uF ,16V  [C1210H2_5]
C102  1uF/16V  [RC0805]
C105  1uF  [RC0402]
C144  100nF  [RC0603]
C145  100uF  [C1210H2_5]
C151  47uF ,16V  [C1210H2_5]
C152  22uF ,6.3V  [RC0603]
C153  10nF  [RC0402]
D6  MBRS340  [DO-214AB]
D7  MBRS340  [DO-214AB]
D8  TVS diode ,15V,1500W,BiDirectional  [DO-214AB]
DS3  LED-Yellow  [LED-1206]
FB7  120 Ohm@3.5A  [1206]
FB8  120 Ohm@3.5A  [1206]
J8  DC Jack 10A  [PJ-0810-TH]
L20  4.7uH , 3.4A  [IND7_3x7_3SM]
L21  IND_DELTA_MPL73-2R2_2.2uH_14A  [IND7x7_2SM]
L22  IND 2.2uH  [IND4_3x4_7SM]
P21  HDR1X2  [1X2THHDR]
P25  1x6HDR  [1x6THHDR]
R60  470K  [RC0402]
R61  6.19k 1%  [RC0402]
R62  348R/1%  [RC0402]
R64  40.2k  1%  [RC0402]
R66  2.37K/1%  [RC0402]
R68  200K/1%  [RC0402]
R69  28.7K/1%  [RC0402]
R70  10.5K/1%  [RC0402]
R71  2K/1%  [RC0402]
R72  6.19k 1%  [RC0402]
R73  40.2k  1%  [RC0402]
R74  1K/1%  [RC0402]
R75  10K/1%  [RC0402]
R76  6.19k 1%  [RC0402]
R78  0R  [RC0402]
R79  0R  [RC0402]
R80  0R  [RC0402]
R88  10K/1%  [RC0402]
R89  0R  [RC0402]
R90  0R  [RC0402]
R91  10K/1%  [RC0402]
R92  10K/1%  [RC0402]
R93  10K/1%  [RC0402]
R94  10K/1%  [RC0402]
R105  30K/1%  [RC0402]
R106  10K/1%  [RC0402]
R107  10K/1%  [RC0402]
R108  0R  [RC0402]
TP1  TESTPOINT  [TP1x1]
TP2  TESTPOINT  [TP1x1]
U14  RT8272  [PSOP-8-2X2]
U15  FAN2110  [MO-220W6050C-3X]
U16  RT8272  [PSOP-8-2X2]
U19  RT9022  [SC70-6]

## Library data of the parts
C1 = 100nF,_10V,_X7R,_10%,_0402_11: CLABCONF0: =SB-T54
C2 C27 = 100nF,_10V,_X7R,_10%,_0402_8: CLABCONF0: =SB-T54
C3 C30 C37 C111 C139 C148 = 100nF,_10V,_X7R,_10%,_0402_4: CLABCONF0: =SB-T54
C4 = 100nF,_10V,_X7R,_10%,_0402_10: CLABCONF0: =SB-T54
C5 C15 C23 C40 C74 C85 C147 = 100nF,_10V,_X7R,_10%,_0402_2: CLABCONF0: =SB-T54
C6 C13 C22 C41 C58 C88 C155 = 100nF,_10V,_X7R,_10%,_0402: CLABCONF0: =SB-T54
C7 C28 = 100nF,_10V,_X7R,_10%,_0402_9: CLABCONF0: =SB-T54
C8 C18 C34 C72 = 100nF,_10V,_X7R,_10%,_0402_7: CLABCONF0: =SB-T54
C9 C16 C35 C60 C154 = 100nF,_10V,_X7R,_10%,_0402_6: CLABCONF0: =SB-T54
C10 C14 C29 C123 C141 C150 = 100nF,_10V,_X7R,_10%,_0402_5: CLABCONF0: =SB-T54
C11 C17 C25 C42 C61 C137 = 100nF,_10V,_X7R,_10%,_0402_3: CLABCONF0: =SB-T54
C12 C24 C39 C98 C133 C149 = 100nF,_10V,_X7R,_10%,_0402_1: CLABCONF0: =SB-T54
C106 = 1nF,_2KV,SMD_1812,_X7R,_10%: CLABCONF0: =DNP
C107 C116 C120 C140 = 22uF,6.3V,X5R_3: CLABCONF0: =SB-T54; P/N: 151B22610S
C108 C112 C117 C122 C135 = 22uF,6.3V,X5R_1: CLABCONF0: =SB-T54; P/N: 151B22610S
C109 C115 C119 C121 C138 = 22uF,6.3V,X5R_2: CLABCONF0: =SB-T54; P/N: 151B22610S
C110 C113 C118 C129 C134 C146 C152 = 22uF,6.3V,X5R: CLABCONF0: =SB-T54; P/N: 151B22610S
FB1 FB4 FB8 FB9 = Ferrite_bead_,_120_Ohm@3A: CLABCONF0: =SB-T54
H1 H2 = Hole,_Plated,_M2,_5mm._ext.: CLABCONF0: =DNP
P18 = SODIMM-204_26: CLABCONF0: =SB-T54
TP1-TP3 = TESTPOINT: CLABCONF0: =DNP; P/N: 188Z10020S
C20 = 100nF,_10V,_X7R,_10%,_0402_8: CLABCONF0: =SB-T54; Group: LAN2
C114 = 100nF,_10V,_X7R,_10%,_0402_1: CLABCONF0: =SB-T54; Group: LAN2
D1 D2 D4 D16 = BAT54WS: CLABCONF0: =SB-T54
D9-D15 = BAT54WS: CLABCONF0: =DNP
F1-F4 = Fuse,_0.75A_Ih,_1.5A_It: CLABCONF0: =SB-T54
J1 J2 = HDMI_Connector: CLABCONF0: =SB-T54
L1-L4 L6-L19 = ESD_CHOKE_DIFFx2_10: CLABCONF0: =SB-T54; P/N: 142D11801S
Q1-Q10 = N-MOSFET,NDS335N,100mOhm@2.5V: CLABCONF0: =SB-T54
R1 R103 = 255R_1%,0402: CLABCONF0: =SB-T54
R4 R102 = 255R_1%,0402_1: CLABCONF0: =SB-T54
R5 R17 R35 R51 R57 R75 = 10K,1%,0402,1_16W: CLABCONF0: =SB-T54
R6 = 10K,1%,0402,1_16W_4: CLABCONF0: =SB-T54
R7 R19 = 33R,5%,0402,1_16W: CLABCONF0: =SB-T54
R9 R106 = 10K,1%,0402,1_16W_6: CLABCONF0: =SB-T54
R11 R24 = 2.2K,5%,0402.1_16W_3: CLABCONF0: =SB-T54
R12 R23 R83 = 2.2K,5%,0402.1_16W_2: CLABCONF0: =SB-T54
R13 R21 R33 = 2.2K,5%,0402.1_16W_1: CLABCONF0: =SB-T54
R14 R22 R84 = 2.2K,5%,0402.1_16W: CLABCONF0: =SB-T54
R16 R34 R91 = 10K,1%,0402,1_16W_3: CLABCONF0: =SB-T54
R30 R81 = 0R,_0402: CLABCONF0: =SB-T54
R29 R82 = 0R,_0402_1: CLABCONF0: =DNP
R78 R95 = 0R,_0402_2: CLABCONF0: =SB-T54
R96 = 100K,_0402: CLABCONF0: =SB-T54
R64 R97 = 40.2k_,1%: CLABCONF0: =SB-T54
R31 R36 R98 R104 = 10K,1%,0402,1_16W_1: CLABCONF0: =SB-T54
R53 R88 R99 = 10K,1%,0402,1_16W_2: CLABCONF0: =SB-T54
R92 R100 = 10K,1%,0402,1_16W_5: CLABCONF0: =SB-T54
RN1 RN2 RN4 = RN,10K,8P4R@0805: CLABCONF0: =SB-T54
U1 = tfp513_0: CLABCONF0: =SB-T54; P/N: 116A01640S
U6 U8 U9 U20 = IP4220CZ6_0: CLABCONF0: =SB-T54
D3 = ZENER_24V_500mW_SOD-123: CLABCONF0: =SB-T54
L5 = IND,47uH,220mA,IND1812_2: CLABCONF0: =SB-T54; P/N: 147A22000S
P3 = FPC_50_05mm: CLABCONF0: =SB-T54
P27 = 1x4_HDR,TH_0: CLABCONF0: =SB-T54; P/N: 190C00400
R18 = 33R,5%,0402,1_16W_1: CLABCONF0: =SB-T54
R25 R74 = 1K,1%,0402,1_16W: CLABCONF0: =SB-T54
R26 = 1K,1%,0402,1_16W_1: CLABCONF0: =SB-T54
R27 = 2.2R,5%,0402,1_16W_1: CLABCONF0: =SB-T54
R28 = 2.2R,5%,0402,1_16W: CLABCONF0: =SB-T54
U2 U3 = 74AVC16T245: CLABCONF0: =SB-T54; P/N: 106RV2451S
U4 = AIC1647: CLABCONF0: =SB-T54
P7 P20 = HDR_2x12_100MIL: CLABCONF0: =SB-T54
P8 = mini_PCIe_0: CLABCONF0: =SB-T54; P/N: 182K05201S
P22 = mini_PCIe_latch: CLABCONF0: =SB-T54; P/N: 203H10031
P23 = mini_PCIe_latch: CLABCONF0: =DNP; P/N: 203H10031
R32 = 17.8k_,1%,0402: CLABCONF0: =SB-T54
R101 = 10K,1%,0402,1_16W: CLABCONF0: =DNP
U5 = 24C02,_serial_EE,_2KB,_I2C: CLABCONF0: =SB-T54
C59 C62 C79 C105 = 1uF,X5R,6.3V,0402: CLABCONF0: =SB-T54
P9 = SDIO_SLOT: CLABCONF0: =SB-T54
P11 = Ultra_Mini_Serial_Connector: CLABCONF0: =SB-T54
P12 P17 P24 = HDR_2x12_100MIL_0: CLABCONF0: =SB-T54; P/N: 190C00801S
RN3 = RN,8.2K,10P8R@1206: CLABCONF0: =DNP
U17 U18 = TXB0104_0: CLABCONF0: =SB-T54; P/N: 116A10030S
C70 = 220nF,_50V,_X7R,_0805: CLABCONF0: =SB-T54
C80 = 220pF,50V,NPO,0603: CLABCONF0: =SB-T54
C132 = 22uF,6.3V,X5R_5: CLABCONF0: =SB-T54; P/N: 151B22610S
C136 = 22uF,6.3V,X5R_4: CLABCONF0: =SB-T54; P/N: 151B22610S
C156 = 22uF,6.3V,X5R_6: CLABCONF0: =SB-T54; P/N: 151B22610S
D5 = BAT54A: CLABCONF0: =SB-T54; P/N: 130E05403S
FB2 FB7 = Ferrite_bead_,_120_Ohm@3A_1: CLABCONF0: =SB-T54
FB3 = Ferrite_bead_,_120_Ohm@3A_3: CLABCONF0: =SB-T54
FB5 = Ferrite_bead_,_120_Ohm@3A_2: CLABCONF0: =SB-T54
FB6 = Ferrite_bead_,_120_Ohm@3A_5: CLABCONF0: =SB-T54
FB10 = Ferrite_bead_,_120_Ohm@3A_4: CLABCONF0: =SB-T54
FB11 = Ferrite_bead_,_120_Ohm@3A_6: CLABCONF0: =SB-T54
J4-J6 = AUDIO_JACK_3.5mm,_no_sw.,_SMT: CLABCONF0: =SB-T54
P13 = Conn.,_RJ45,_Y_G_LED,_TH: CLABCONF0: =SB-T54
P15 = USB_A-TYPE_DOUBLE_TH: CLABCONF0: =SB-T54; Group: Front Panel
P16 = USB3_OTGMINIB_5: CLABCONF0: =SB-T54; P/N: 180K01000S
P26 = USB_Conn.,_Fem,_Type_A_,_TH,_RA: CLABCONF0: =SB-T54
R48 = 348R,1%,0402,1_16W_1: CLABCONF0: =SB-T54
R49 R62 = 348R,1%,0402,1_16W: CLABCONF0: =SB-T54
R50 = 47K,_0402_1: CLABCONF0: =SB-T54; P/N: 161C68001S
R52 = 47K,_0402: CLABCONF0: =SB-T54
U11 = RYC8220-1M_DUAL_USB_PWR_SWITCH: CLABCONF0: =SB-T54
DS4 = LED-RED_1206: CLABCONF0: =SB-T54
DS5 = LED,_Chip_3x1mm,_R_A,_Green: CLABCONF0: =SB-T54; P/N: 139A10020S
P19 P21 = HDR_1X2_100MIL_TH: CLABCONF0: =SB-T54
SW1 SW2 = TACT_SW_6x6mm_SMT: CLABCONF0: =SB-T54
SW3 = Switch,_Push-B,_RA: CLABCONF0: =SB-T54
BH1 = BATT_HOLDER_5: CLABCONF0: =DNP; P/N: 190Z00202S
BT1 = ML1020: CLABCONF0: =SB-T54
C81 = Cap.,_47uF,_16V,_X5R_1: CLABCONF0: =SB-T54
C83 = 10nF,_25V,_X7R,_10%,_0402_1: CLABCONF0: =SB-T54
C84 = Cap_1uF,X5R,6.3V,0402: CLABCONF0: =SB-T54
C86 = 2.2nF,_50V,_X7R,_10%,_0402_2: CLABCONF0: =SB-T54
C87 = Cap.,_47uF,_16V,_X5R_2: CLABCONF0: =SB-T54
C89-C91 C100 = 100uF,_6.3V,_X5R,_20%,_1206: CLABCONF0: =SB-T54
C93 = Cap.,680pF,0402: CLABCONF0: =SB-T54
C94 = 10nF,_25V,_X7R,_10%,_0402_2: CLABCONF0: =SB-T54
C95 = 2.2nF,_50V,_X7R,_10%,_0402_1: CLABCONF0: =SB-T54
C96 = 2.2nF,_50V,_X7R,_10%,_0402: CLABCONF0: =SB-T54
C97 = Cap.,_47uF,_16V,_X5R: CLABCONF0: =SB-T54
C99 = 100pF,_50V,_NPO,_5%,_0402: CLABCONF0: =SB-T54; Group: Always
C101 = Cap.,_47uF,_16V,_X5R_3: CLABCONF0: =SB-T54
C102 = 1uF,_16V,_X7R,_20%,_0805: CLABCONF0: =SB-T54
C144 = 100nF,_10V,_X7R,_10%,_0402_3: CLABCONF0: =DNP; P/N: 151K10410S
C145 = 100uF,_6.3V,_X5R,_20%,_1210: CLABCONF0: =SB-T54; P/N: 151C10780S
C151 = Cap.,_47uF,_16V,_X5R_4: CLABCONF0: =SB-T54
C153 = 10nF,_25V,_X7R,_10%,_0402: CLABCONF0: =SB-T54
D6 D7 = Diode_,MBRS340_,3A_0: CLABCONF0: =SB-T54
D8 = Diode_,TVS_,15V,1500W_0: CLABCONF0: =SB-T54; P/N: 132D00150S
DS3 = LED-Yellow_1206: CLABCONF0: =SB-T54
J8 = DC_Jack_,5.5_2_0.5,10A,20V: CLABCONF0: =SB-T54
L20 = Inductor_,4.7uH_,3.4A: CLABCONF0: =SB-T54
L21 = IND_DELTA_MPL73-2R2_2.2uH_14A_1: CLABCONF0: =SB-T54
L22 = IND_DELTA_MPL73-2R2_2.2uH_14A: CLABCONF0: =SB-T54; Group: Always; Isat: 5A; P/N: 147A2R204S
P25 = HDR_1x8_100_MIL_TH_1: CLABCONF0: =DNP; P/N: 190C00600
R60 = 470K,_0402: CLABCONF0: =SB-T54
R61 = Res.,6.19k,1%_2: CLABCONF0: =SB-T54
R66 = 2.37K_1%,_0402: CLABCONF0: =SB-T54
R68 = 200K,1%,0402,1_16W: CLABCONF0: =SB-T54
R69 = 28.7K_1%,_0402: CLABCONF0: =SB-T54
R70 = 10.5K_1%,0402: CLABCONF0: =SB-T54
R71 = 2K,1%,0402,1_16W: CLABCONF0: =SB-T54
R72 = Res.,6.19k,1%_1: CLABCONF0: =SB-T54
R73 = 40.2k_,1%_1: CLABCONF0: =SB-T54
R76 = Res.,6.19k,1%: CLABCONF0: =SB-T54
R79 = 0R,_0402_1: CLABCONF0: =SB-T54
R80 = 0R,_0402: CLABCONF0: =DNP
R89 = 0R,_0402_4: CLABCONF0: =DNP
R90 = 0R,_0402_5: CLABCONF0: =SB-T54
R93 = 10K,1%,0402,1_16W_4: CLABCONF0: =DNP
R94 = 10K,1%,0402,1_16W_1: CLABCONF0: =DNP
R105 = 30K,1%,0402,1_16W: CLABCONF0: =SB-T54
R107 = 10K,1%,0402,1_16W_7: CLABCONF0: =DNP
R108 = 0R,_0402_3: CLABCONF0: =SB-T54
U14 U16 = RT8272,Converter,3A,24V: CLABCONF0: =SB-T54
U15 = IC,Sync_Buck_Reg.,10A,3-24V: CLABCONF0: =SB-T54
U19 = RT9022,LDO,20_5V: CLABCONF0: =SB-T54

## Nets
1V8: C27.1 C28.1 C29.1 C30.1 C100.2 C117.1 C123.2 C148.1 C149.1 L22.2 P24.2 P25.6 Q1.1(G) Q2.1(G) Q3.1(G) Q4.1(G) Q5.1(G) Q6.1(G) Q7.1(G) Q10.3(D) R9.2 R11.2 R13.2 R21.2 R22.2 R30.1 R33.2 R35.1 R36.1 R53.1 R72.1 R82.1 R83.2 R84.2 R101.2 SW1.1 SW1.3 U2.A1(T/~{R}1) U2.C4(VCCA) U2.H4(VCCA) U2.K1(T/~{R}2) U3.A1(T/~{R}1) U3.C4(VCCA) U3.H4(VCCA) U3.K1(T/~{R}2) U5.8(VCC) U17.1(VCCA) U17.8(OE) U18.1(VCCA) U18.8(OE)
1V8_CMP: C95.1 U16.6(COMP)
1V8_RC: C95.2 R73.1
1V8_SBT: C94.1 U16.1(BOOT)
1V8_SBYFB: R72.2 R76.1 U16.5(FB)
1V8_SS: C98.2 U16.8(SS)
1V8_SW: C94.2 D7.CATHODE L22.1 U16.3(SW)
1V8LVDS: C122.1 P7.2 R30.2
3V3: C13.2 C14.2 C15.2 C16.2 C17.2 C18.2 C22.1 C23.1 C24.1 C25.1 C34.1 C35.1 C37.2 C39.2 C40.2 C41.2 C42.2 C58.1 C59.1 C60.1 C61.1 C62.1 C91.2 C111.2 C112.1 C116.1 C118.1 C119.1 C120.1 C129.1 C147.1 C150.1 L5.1 L20.2 P3.3 P3.6 P8.2(+3.3V_1) P8.24(+3.3V_AUX) P8.39(RSVD6) P8.41(RSVD7) P8.52(+3.3V_2) P9.4(VDD) P25.4 R17.2 R23.2 R24.2 R29.1 R61.1 R62.2 R81.1 R95.1 R96.1 R102.1 R103.1 RN2.8(RA2) RN3.5(COM1) RN3.10(COM2) RN4.1(RA1) RN4.2(RB1) U1.1(DVDD) U1.12(DVDD) U1.18(PVDD) U1.23(TVDD) U1.29(TVDD) U1.33(DVDD) U2.C3(VCCB) U2.H3(VCCB) U3.C3(VCCB) U3.H3(VCCB) U4.5(VIN) U8.5(VBUS) U9.5(VBUS) U17.14(VCCB) U18.14(VCCB)
3V3_CMP: C86.1 U14.6(COMP)
3V3_RC: C86.2 R64.1
3V3_SBT: C83.1 U14.1(BOOT)
3V3_SBYFB: R61.2 R66.1 U14.5(FB)
3V3_SS: C88.2 U14.8(SS)
3V3_SW: C83.2 D6.CATHODE L20.1 U14.3(SW)
3V3LVDS: C121.1 P7.1 R29.2
5V0: C1.1 C2.1 C3.1 C4.1 C5.1 C6.1 C7.1 C8.1 C9.1 C10.1 C11.1 C12.1 C20.1 C72.1 C89.2 C90.2 C93.1 C107.1 C108.1 C109.1 C110.1 C113.1 C132.1 C133.1 C134.1 F1.2 F2.2 F3.2 F4.2 L21.2 P18.10(VSYS1) P18.28(VSYS2) P18.46(VSYS3) P18.64(VSYS4) P18.78(VSYS5) P18.96(VSYS6) P18.114(VSYS7) P18.132(VSYS8) P18.150(VSYS9) P18.168(VSYS10) P18.186(VSYS11) P18.204(VSYS12) P25.2 R12.2 R14.2 R70.2 R78.1 R79.2 R89.1 RN2.5(RD2) RN2.6(RC2) RN2.7(RB2) U11.7(VCC)
5V_PROT1: D4.2(ANODE) F2.1
5V_VCC: C84.1 C152.1 R90.1 R105.1 U15.15(VCC) U19.3(Vout)
12V: C81.1 C87.1 C97.1 C101.1 C102.1 C144.2 C145.2 C151.1 FB7.2 P25.1 R60.1 R88.1 R108.2 U14.2(Vin) U15.2(Vin) U15.3(Vin) U15.4(Vin) U15.5(Vin) U15.P2(Vin) U16.2(Vin) U19.1(Vin) U19.6(EN)
GND: BH1.2N(N) BT1.2(NEG) C1.2 C2.2 C3.2 C4.2 C5.2 C6.2 C7.2 C8.2 C9.2 C10.2 C11.2 C12.2 C13.1 C14.1 C15.1 C16.1 C17.1 C18.1 C20.2 C22.2 C23.2 C24.2 C25.2 C27.2 C28.2 C29.2 C30.2 C34.2 C35.2 C37.1 C39.1 C40.1 C41.1 C42.1 C58.2 C59.2 C60.2 C61.2 C62.2 C70.2 C72.2 C80.1 C81.2 C84.2 C87.2 C88.1 C89.1 C90.1 C91.1 C97.2 C98.1 C100.1 C101.2 C102.2 C105.2 C106.2 C107.2 C108.2 C109.2 C110.2 C111.1 C112.2 C113.2 C114.2 C115.2 C116.2 C117.2 C118.2 C119.2 C120.2 C121.2 C122.2 C123.1 C129.2 C132.2 C133.2 C134.2 C144.1 C145.1 C146.2 C147.2 C148.2 C149.2 C150.2 C151.2 C152.2 C153.2 C156.2 D6.ANODE D7.ANODE DS3.CATHODE FB5.1 FB8.2 FB9.1 FB10.1 FB11.1 H1.1 H2.1 J1.2(D2_Shield) J1.5(D1_Shield) J1.8(D0_Shield) J1.11(CK_Shield) J1.17(GND) J2.2(D2_Shield) J2.5(D1_Shield) J2.8(D0_Shield) J2.11(CK_Shield) J2.17(GND) J4.1(COM) J5.1(COM) J6.1(COM) L1.5(GND) L1.6(GND) L2.5(GND) L2.6(GND) L3.5(GND) L3.6(GND) L4.5(GND) L4.6(GND) L6.5(GND) L6.6(GND) L7.5(GND) L7.6(GND) L8.5(GND) L8.6(GND) L9.5(GND) L9.6(GND) L10.5(GND) L10.6(GND) L11.5(GND) L11.6(GND) L12.5(GND) L12.6(GND) L13.5(GND) L13.6(GND) L14.5(GND) L14.6(GND) L15.5(GND) L15.6(GND) L16.5(GND) L16.6(GND) L17.5(GND) L17.6(GND) L18.5(GND) L18.6(GND) L19.5(GND) L19.6(GND) P3.9 P3.18 P3.24 P3.26 P3.46 P7.5 P7.6 P7.9 P7.10 P7.13 P7.14 P7.17 P7.18 P7.21 P7.22 P8.4(GND7) P8.9(GND1) P8.15(GND2) P8.18(GND8) P8.21(GND3) P8.26(GND9) P8.27(GND4) P8.29(GND5) P8.34(GND10) P8.35(GND6) P8.37(RSVD5) P8.40(GND11) P8.50(GND12) P9.3(VSS1) P9.6(VSS2) P9.10(GND) P9.13(GND) P9.14(GND) P9.15(GND) P11.5 P11.6 P11.8 P13.4(CHGND1) P13.5(CHGND2) P18.1(GND1) P18.19(GND2) P18.37(GND3) P18.55(GND4) P18.71(GND5) P18.87(GND6) P18.105(GND7) P18.123(GND8) P18.141(GND9) P18.159(GND10) P18.177(GND11) P18.195(GND12) P19.1 P20.24 P24.7 P25.3 P25.5 Q8.2(S) Q9.2(S) R25.1 R27.2 R31.1 R34.2 R52.2 R57.2 R64.2 R66.2 R68.2 R69.1 R71.2 R73.2 R76.2 R80.2 R97.2 R99.2 R100.2 R104.2 R106.1 RN1.1(RA1) RN1.2(RB1) SW2.2 SW2.4 SW3.2 U1.16(DGND) U1.17(PGND) U1.20(TGND) U1.26(TGND) U1.32(TGND) U1.34(RSVD2) U1.48(DGND) U1.56(IDCK-) U1.64(DGND) U2.A6(\\~{O}E1) U2.B3(GND) U2.B4(GND) U2.D3(GND) U2.D4(GND) U2.G3(GND) U2.G4(GND) U2.J3(GND) U2.J4(GND) U2.K6(\\~{O}E2) U3.A6(\\~{O}E1) U3.B3(GND) U3.B4(GND) U3.D3(GND) U3.D4(GND) U3.G3(GND) U3.G4(GND) U3.J3(GND) U3.J4(GND) U3.K6(\\~{O}E2) U4.2(GND) U5.1(A0) U5.2(A1) U5.3(A2) U5.4(GND) U6.2(GND) U8.2(GND) U9.2(GND) U11.6(GND) U14.4(GND) U14.9(PAD) U15.16(AGND) U15.21(PGND) U15.22(PGND) U15.23(PGND) U15.P3(PGND) U16.4(GND) U16.9(PAD) U17.7(GND) U18.7(GND) U19.2(GND) U20.2(GND)
GND_IN: FB8.1 J8.2(R)
GND_OTG: C140.2 C141.2 FB11.2 P16.5(GND) P16.8(GNDD)
GND_USB: C74.2 C135.2 C136.2 C137.2 FB5.2 P15.4(GND) P15.8(GND)
GND_USB3: C138.2 C139.2 FB10.2 P26.4(GND)
V5_ADJ: C93.2 R74.1
V5_BOOT: C85.1 U15.1(BOOT)
V5_CCOMP: C96.1 C99.1 U15.20(COMP)
V5_CMED: C96.2 R75.1
V5_FB: C99.2 R70.1 R71.1 R74.2 R75.2 U15.19(FB)
V5_LX: C85.2 L21.1 U15.6(SW) U15.7(SW) U15.8(SW) U15.9(SW) U15.10(SW) U15.11(SW) U15.12(SW) U15.P1(SW)
V5_RAMP: R60.2 U15.25(RAMP)
V5_RLIM: R68.1 U15.17(ILIM)
V5_RT: R69.2 U15.18(R(T))
VBAT_SENSE: P18.179(RESERVED2) R79.1
VBUS_5V_OTG: C140.1 C141.1 FB6.1 P18.180(USBOTG_VBUS)
VBUS_EN_REQ: P18.156(USB_PWREN) RN4.8(RA2) U11.1(EN_A)
VBUS_nOVERCURRENT: P18.162(USB_nOVC) RN4.7(RB2) U11.2(FLG_A)
VCC_USB_1: C74.1 C135.1 FB3.2 P15.1(VBUS)
VCC_USB_1FB: F3.1 FB3.1
VCC_USB_2: C136.1 C137.1 FB4.2 P15.5(VBUS)
VCC_USB_2FB: F4.1 FB4.1
VCC_USB_3: C138.1 C139.1 FB2.2 P26.1(VBUS)
VCC_USB_3FB: FB2.1 U11.8(OUT_A)
VDD3A_ETH: C70.1 C156.1 P13.3(TDC) P13.6(RDC) P18.2(3V3A_ETH_PHY) R48.1 R49.1
ABEDMIC_CLK2/ABEMCBSP1_FSX/ABEMCASP_AMUTEIN/GPIO4_101: P18.145(I2S1_FSX) P20.22
ABEDMIC_CLK3/ABEMCBSP1_DX/ABEMCASP_ACLKX/GPIO4_102: P18.139(I2S1_DOUT) P20.23
ABEMCBSP2_FSX/ABEMCASP_AFSX/GPIO4_107: P18.200(RESERVED6) P24.5
ABESLIMBUS1_CLOCK/ABEMCBSP1_CLKX/GPIO4_103: P18.137(I2S1_CLKX) P20.21
ABESLIMBUS1_DATA/ABEMCBSP1_DR/GPIO4_104: P18.143(I2S1_DIN) P20.20
ALT_BOOT: P18.185(ALT_BOOT) R57.1 SW1.2 SW1.4
ALW_EN_5: C105.1 U15.14(EN)
AMPR: C79.2 R51.1
ANDERS_CLK: P3.25 R18.2
B0: P3.44 U2.B2(B0)
B1: P3.43 U2.B1
B2: P3.42 U2.C2(B2)
B3: P3.41 U2.C1(B3)
B4: P3.40 U2.D2(B4)
B5: P3.39 U2.D1(B5)
B6: P3.38 U2.E2(B6)
B7: P3.37 U2.E1(B7)
BCKL_PWM: R25.2 U3.J1(B14) U4.4(\\~{SHD}N)
BCKLIGHT_FB: D3.2(ANODE) R26.2 U4.3(FB)
BKBAT: P18.183(BACKUP_BAT) P21.2 R107.1
BSEL: R6.2 U1.15(BSEL/SCL)
BTP: BH1.1P(P) BH1.3P(P) BT1.1(POS) P21.1
CAM_GLOBALRESET/CPI_FID/GPIO8_226: P18.99(PCAM_RESET) P20.14
CAM_SHUTTER/SYS_NODEID0/GPIO8_224: P18.81(PCAM_SHUTTER) P20.10
CAM_STROBE/SYS_NODEID1/GPIO8_225: P18.93(PCAM_STROBE) P20.12
CHASSIS: C106.1 D8.ANODE FB9.2 J1.20(SHELL1) J1.21(SHELL2) J2.20(SHELL1) J2.21(SHELL2) J8.3(Plastic) J8.SH1 J8.SH2 J8.SH3 J8.SH4 P11.9(CHASSIS) P11.10(CHASSIS) P11.11(CHASSIS) P11.12(CHASSIS) P13.13(SHLD1) P13.14(SHLD2) P15.9(SHIELD) P15.10(SHIELD) P15.11(SHIELD) P15.12(SHIELD) P16.NC1(CHASSIS) P16.NC2(CHASSIS) P16.NC3(CHASSIS) P16.NC4(CHASSIS) P16.NC5(CHASSIS) P16.NC6(CHASSIS) P26.5(SHELL_1) P26.6(SHELL_2)
COLD_RESET_IN: P18.171(COLD_RESET_IN) SW2.1 SW2.3
CSIPORTA_LANE0X/CPI_PCLK/GPIO8_IN236: P18.95(PCAM_PCLK) P20.6
CSIPORTA_LANE0Y/CPI_WEN/GPIO8_IN237: P18.97(PCAM_WEN) P20.8
CSIPORTA_LANE1X/CPI_DATA1/GPIO8_IN239: P18.103(PCAM_DAT1) P20.2
CSIPORTA_LANE1Y/CPI_DATA0/GPIO8_IN238: P18.101(PCAM_DAT0) P20.4
CSIPORTA_LANE2X/CPI_DATA3/GPIO8_IN241: P18.91(PCAM_DAT3) P20.11
CSIPORTA_LANE2Y/CPI_DATA2/GPIO8_IN240: P18.89(PCAM_DAT2) P20.9
CSIPORTA_LANE3X/CPI_DATA4/GPIO8_IN242: P18.77(PCAM_DAT4) P20.5
CSIPORTA_LANE3Y/CPI_DATA5/GPIO8_IN243: P18.79(PCAM_DAT5) P20.7
CSIPORTA_LANE4X/CPI_DATA6/GPIO8_IN244: P18.83(PCAM_DAT6) P20.1
CSIPORTA_LANE4Y/CPI_DATA7/GPIO8_IN245: P18.85(PCAM_DAT7) P20.3
CSIPORTB_LANE0X/CPI_DATA12/GPIO8_IN246: P18.131(PCIE_RX+) P20.13
CSIPORTB_LANE0Y/CPI_DATA13/GPIO8_IN247: P18.133(PCIE_RX-) P20.15
CSIPORTB_LANE1X/CPI_DATA15/GPIO8_IN249: P18.125(PCIE_TX+) P20.17
CSIPORTB_LANE1Y/CPI_DATA14/GPIO8_IN248: P18.127(PCIE_TX-) P20.19
CSIPORTB_LANE2X/CPI_VSYNCIN/GPIO8_IN251: P18.113(PCAM_VSYNC) P20.16
CSIPORTB_LANE2Y/CPI_HSYNCIN/GPIO8_IN250: P18.115(PCAM_HSYNC) P20.18
CSIPORTC_LANE0X/CPI_DATA9/GPIO8_IN253: D16.2(ANODE) P18.109(PCAM_DAT9)
CSIPORTC_LANE0Y/CPI_DATA8/GPIO8_IN252: P18.107(PCAM_DAT8) P24.4
CSIPORTC_LANE1Y/CPI_DATA10/GPIO8_IN254: P18.121(PCIE_REFCLK-) Q10.2(S) R104.1
D0M: L3.3 U1.24(TXD0-)
D0P: L3.4 U1.25(TXD0+)
D1M: L2.3 U1.27(TXD1-)
D1P: L2.4 U1.28(TXD1+)
D2M: L1.3 U1.30(TXD2-)
D2P: L1.4 U1.31(TXD2+)
DCLKM: L4.3 U1.21(TXC-)
DCLKP: L4.4 U1.22(TXC+)
DDC_SCL_5V: D14.1(CATHODE) J2.15(DDC_CLK) Q6.3(D) RN2.3(RC1) U6.6(IO4)
DDC_SDA_5V: D15.1(CATHODE) J2.16(DDC_DATA) Q7.3(D) RN2.4(RD1) U6.4(IO3)
DE: P3.23 U3.G1(B10)
DESKEW_LSB: RN1.5(RD2) U1.8(DK1)
DESKEW_MIDDLE_BIT: RN1.8(RA2) U1.7(DK2)
DESKEW_MSB: RN1.7(RB2) U1.6(DK3)
DRM_EMU0/GPIO1_WK6: P18.152(GPIO1) Q8.1(G)
DRM_EMU1/GPIO1_WK7: P18.154(GPIO2) Q9.1(G)
DSEL: R99.1 U1.14(DSEL/SDA)
DSIPORTA_TE0/GPIO6_189: P7.24 P18.75(RESERVED1) R53.2
DVI_5V: D1.1(CATHODE) J1.18(+5V) U20.3(IO2)
DVI_5V_D: D1.2(ANODE) F1.1
DVI_CLK: R7.2 U1.57(IDCK+)
DVI_CTR: C114.1 C115.1 R1.1 R5.1 R6.1 R16.1 R81.2 R82.2 R98.1 RN1.3(RC1) RN1.4(RD1)
DVI_DESKEW_ENABLE: R16.2 U1.35(DKEN)
DVI_RISINGEDGE_ENABLE: R5.2 U1.9(HTPLG)
DVI_TXD0+: J1.7(D0+) L3.1
DVI_TXD0-: J1.9(D0-) L3.2
DVI_TXD1+: J1.4(D1+) L2.1
DVI_TXD1-: J1.6(D1-) L2.2
DVI_TXD2+: J1.1(D2+) L1.1
DVI_TXD2-: J1.3(D2-) L1.2
DVI_TXDC+: J1.10(CK+) L4.1
DVI_TXDC-: J1.12(CK-) L4.2
EEPROM_WP: R31.2 R101.1 U5.7(WP)
EN_1V8: R92.2 R94.2 U16.7(EN)
EN_3V3: R91.2 R93.2 U14.7(EN)
ENET_nFDX_LED: D5.1(ANODE1) P18.22(ETH_LED3)
ENET_nLNKA_LED: P13.11(LK) P18.4(ETH_LED2_ACT)
ENET_RXN: P13.8(RDN) P18.12(MDI1-/RX-)
ENET_RXP: P13.7(RDP) P18.14(MDI1+/RX+)
ENET_SPD_n100M_LED: D5.2(ANODE2) P18.16(ETH_LED1_SPD)
ENET_TXN: P13.2(TDN) P18.6(MDI0-/TX-)
ENET_TXP: P13.1(TDP) P18.8(MDI0+/TX+)
EPROM_WP: P18.189(EEPROM_WP) P19.2
F_S_ADJ: R1.2 R4.1
FULL_SCALE_ADJUST: R4.2 U1.19(TFADJ)
G0: P3.36 U2.F1(B8)
G1: P3.35 U2.F2(B9)
G2: P3.34 U2.G1(B10)
G3: P3.33 U2.G2(B11)
G4: P3.32 U2.H1(B12)
G5: P3.31 U2.H2(B13)
G6: P3.30 U2.J1(B14)
G7: P3.29 U2.J2(B15)
GPADC_IN0: P17.7 P18.175
GPADC_IN1: P17.5 P18.173
GPADC_IN2: P17.3 P18.169
GPADC_VREF: P17.1 P18.167
GPIO6_182/DISPC_DATA18/KBD_COL0: P18.142(PDISP_DAT18) U1.41(PD18) U3.C5(A2)
GPIO6_183/DISPC_DATA19/KBD_COL1: P18.144(PDISP_DAT19) U1.40(PD19) U3.C6(A3)
GPIO6_184/DISPC_DATA20/KBD_COL2: P18.146(PDISP_DAT20) U1.39(PD20) U3.D5(A4)
GPIO6_185/DISPC_DATA21/KBD_ROW0: P18.148(PDISP_DAT21) U1.38(PD21) U3.D6(A5)
GPIO6_186/DISPC_DATA22/KBD_ROW1: P18.74(PDISP_DAT22) U1.37(PD22) U3.E5(A6)
GPIO6_187/DISPC_DATA23/KBD_ROW2: P18.76(PDISP_DAT23) U1.36(PD23) U3.E6(A7)
GREEN_LED: DS5.ANODE R103.2
GREENLED: DS5.CATHODE Q9.3(D)
HDMI_5V: C146.1 FB1.2 J2.18(+5V) U6.3(IO2)
HDMI_5V_FL: D4.1(CATHODE) FB1.1
HDMI_CEC: D13.1(CATHODE) J2.13(CE_Remote) Q5.3(D) RN2.1(RA1)
HDMI_CEC/GPIO7_192: D13.2(ANODE) P18.34(HDMI_CEC) Q5.2(S) R33.1
HDMI_CLOCKX: L14.4 P18.30(TMDS_CLK+)
HDMI_CLOCKY: L14.3 P18.32(TMDS_CLK-)
HDMI_DATA0X: L13.4 P18.36(TMDS_DAT0+)
HDMI_DATA0Y: L13.3 P18.38(TMDS_DAT0-)
HDMI_DATA1X: L12.4 P18.42(TMDS_DAT1+)
HDMI_DATA1Y: L12.3 P18.44(TMDS_DAT1-)
HDMI_DATA2X: L11.4 P18.48(TMDS_DAT2+)
HDMI_DATA2Y: L11.3 P18.50(TMDS_DAT2-)
HDMI_DDC_SCL/GPIO7_194: D14.2(ANODE) P18.25(TMDS_DDC_SCL) Q6.2(S) R83.1
HDMI_DDC_SDA/GPIO7_195: D15.2(ANODE) P18.31(TMDS_DDC_SDA) Q7.2(S) R84.1
HDMI_HOTPD: J2.19(HP_DET) R32.1 U6.1(IO1)
HDMI_HPD/GPIO7_193: P18.40(TMDS_HPD) R32.2 R34.1
HSYNC: P3.17 U3.H1(B12)
I2C2_SCL/GPIO5_138: D10.2(ANODE) P18.43(I2C2_SCL) Q2.2(S) R13.1
I2C2_SDA/GPIO5_139: D9.2(ANODE) P18.49(I2C2_SDA) Q1.2(S) R11.1
I2C3_SCL/GPIO8_231: P18.129(I2C3_SCL) P24.6
I2C3_SDA/GPIO8_232: P18.135(I2C3_SDA) P24.8
I2C4_SCL/GPIO7_200: D12.2(ANODE) P18.161 Q4.2(S) R21.1 U5.6(SCL)
I2C4_SDA/GPIO7_201: D11.2(ANODE) P18.163 Q3.2(S) R22.1 U5.5(SDA)
ISEL: R100.1 U1.13(ISEL/~{RESET})
LCD_CLK_T: R19.2 U3.F5(A9)
LCD_PCLK: R18.1 U3.F2(B9)
LDO_FB: R105.2 R106.2 U19.4(FB)
LDO_SS: C153.1 U19.5(SS)
LHPOUT: J5.2(L) P18.203(ANALOG_LOUT)
LLINEIN: J4.2(L) P18.199(ANALOG_LIN)
LVDS0_CLK_N: L10.3 P18.35(LVDS_CLK0-)
LVDS0_CLK_P: L10.4 P18.33(LVDS_CLK0+)
LVDS0_CLKN: L10.2 P7.20
LVDS0_CLKP: L10.1 P7.19
LVDS0_N0: L6.2 P7.4
LVDS0_N1: L7.2 P7.8
LVDS0_N2: L8.2 P7.12
LVDS0_N3: L9.2 P7.16
LVDS0_P0: L6.1 P7.3
LVDS0_P1: L7.1 P7.7
LVDS0_P2: L8.1 P7.11
LVDS0_P3: L9.1 P7.15
LVDS0_TX0_N: L6.3 P18.41(LVDS_TX0-)
LVDS0_TX0_P: L6.4 P18.39(LVDS_TX0+)
LVDS0_TX1_N: L7.3 P18.47(LVDS_TX1-)
LVDS0_TX1_P: L7.4 P18.45(LVDS_TX1+)
LVDS0_TX2_N: L8.3 P18.53(LVDS_TX2-)
LVDS0_TX2_P: L8.4 P18.51(LVDS_TX2+)
LVDS0_TX3_N: L9.3 P18.59(LVDS_TX3-)
LVDS0_TX3_P: L9.4 P18.57(LVDS_TX3+)
MCSPI1_CLK/USBD0_ULPIPHY_CLK/GPIO5_140: P3.19 P18.69(SPI_CLK)
MCSPI1_CS0/USBD0_ULPIPHY_DATA0/GPIO5_143: P3.45 P18.58(SPI_CS0)
MCSPI1_CS1/USBD0_ULPIPHY_DATA1/GPIO5_144: P3.20 P18.52(SPI_CS1)
MCSPI1_SIMO/USBD0_ULPIPHY_DIR/GPIO5_142: P3.21 P18.65(SPI_SIMO)
MCSPI1_SOMI/USBD0_ULPIPHY_NXT/GPIO5_141: P3.22 P18.63(SPI_SOMI)
MIC_IN: C79.1 C80.2 J6.2(L) R50.2 R52.1
MICBIAS: P18.191(ANALOG_MICBIAS/MICIN+) R50.1
MICIN: P18.193(ANALOG_MICIN/MICIN-) R51.2
PD_INT: R98.2 U1.10(~{PD})
PG_V5A: R88.2 TP2.1 U15.13(PGOOD)
PMIC_ENABLE1_REQ: P18.198(PER_PWREN_OUT) P24.1
PMIC_PWRON: D16.1(CATHODE) P18.165(PWRON) SW3.3
PMIC_REGEN1: P18.202(PER_PWREN_REQ) R93.1 R94.1
PMID: P18.196(BOOT_PWR_IN) R78.2
POWERGOOD/USB_PSEL: P18.192(RESERVED4) R107.2 TP1.1
R0: P3.28 U3.B2(B0)
R1: P3.27 U3.B1
R2: P3.15 U3.C2(B2)
R3: P3.14 U3.C1(B3)
R4: P3.13 U3.D2(B4)
R5: P3.12 U3.D1(B5)
R6: P3.11 U3.E2(B6)
R7: P3.10 U3.E1(B7)
RED_LED: DS4.ANODE R102.2
REDLED: DS4.CATHODE Q8.3(D)
RFBI_A0/DISPC_DE/KBD_ROW4/GPIO6_165: P18.104(PDISP_DE) U1.2(DE) U3.G6(A10)
RFBI_CS0/DISPC_HSYNC/DRM_EMU3/GPIO6_163: P18.100(PDISP_HSYNC) U1.4(HSYNC) U3.H6(A12)
RFBI_DATA0/DISPC_DATA0/DRM_EMU4/GPIO6_166: P18.106(PDISP_DAT0) U1.63(PD0) U2.B5(A0)
RFBI_DATA1/DISPC_DATA1/UART3_RX_IRRX/DRM_EMU5/GPIO6_167: P18.108(PDISP_DAT1) U1.62(PD1) U2.B6(A1)
RFBI_DATA2/DISPC_DATA2/UART3_TX_IRTX/DRM_EMU6/GPIO6_168: P18.110(PDISP_DAT2) U1.61(PD2) U2.C5(A2)
RFBI_DATA3/DISPC_DATA3/DRM_EMU7/GPIO6_169: P18.112(PDISP_DAT3) U1.60(PD3) U2.C6(A3)
RFBI_DATA4/DISPC_DATA4/DRM_EMU8/GPIO6_170: P18.116(PDISP_DAT4) U1.59(PD4) U2.D5(A4)
RFBI_DATA5/DISPC_DATA5/DRM_EMU9/GPIO6_171: P18.118(PDISP_DAT5) U1.58(PD5) U2.D6(A5)
RFBI_DATA6/DISPC_DATA6/DRM_EMU10/GPIO6_172: P18.120(PDISP_DAT6) U1.55(PD6) U2.E5(A6)
RFBI_DATA7/DISPC_DATA7/DRM_EMU11/GPIO6_173: P18.122(PDISP_DAT7) U1.54(PD7) U2.E6(A7)
RFBI_DATA8/DISPC_DATA8/KBD_COL3/DRM_EMU12/GPIO6_174: P18.124(PDISP_DAT8) U1.53(PD8) U2.F6(A8)
RFBI_DATA9/DISPC_DATA9/KBD_ROW3/DRM_EMU13/GPIO6_175: P18.126(PDISP_DAT9) U1.52(PD9) U2.F5(A9)
RFBI_DATA10/DISPC_DATA10/KBD_ROW8/DRM_EMU14/GPIO6_176: P18.128(PDISP_DAT10) U1.51(PD10) U2.G6(A10)
RFBI_DATA11/DISPC_DATA11/KBD_ROW7/DRM_EMU15/GPIO6_177: P18.130(PDISP_DAT11) U1.50(PD11) U2.G5(A11)
RFBI_DATA12/DISPC_DATA12/KBD_ROW6/DRM_EMU16/GPIO6_178: P18.134(PDISP_DAT12) U1.47(PD12) U2.H6(A12)
RFBI_DATA13/DISPC_DATA13/KBD_COL8/DRM_EMU17/GPIO6_179: P18.136(PDISP_DAT13) U1.46(PD13) U2.H5(A13)
RFBI_DATA14/DISPC_DATA14/KBD_COL7/DRM_EMU18/GPIO6_180: P18.138(PDISP_DAT14) U1.45(PD14) U2.J6(A14)
RFBI_DATA15/MCSPI2_CS1/DISPC_DATA15/KBD_COL6/DRM_EMU19/GPIO6_181: P18.140(PDISP_DAT15) U1.44(PD15) U2.J5(A15)
RFBI_HSYNC0/DISPC_DATA17/KBD_COL5/GPIO6_160: P18.92(PDISP_DAT17) U1.42(PD17) U3.B6(A1)
RFBI_RE/DISPC_PCLK/KBD_COL4/GPIO6_164: P18.98(PDISP_PCLK) R7.1 R19.1
RFBI_TE_VSYNC0/DISPC_DATA16/KBD_ROW5/JTAG_SEL/GPIO6_161: P18.94(PDISP_DAT16) U1.43(PD16) U3.B5(A0)
RFBI_WE/DISPC_VSYNC/DRM_EMU2/GPIO6_162: P18.102(PDISP_VSYNC) U1.5(VSYNC) U3.G5(A11)
RHPOUT: J5.3(R) P18.201(ANALOG_ROUT)
RLINEIN: J4.3(R) P18.197(ANALOG_RIN)
RS232_RXD: P11.3 P18.117(RS232_RX)
RS232_TXD: P11.1 P18.111(RS232_TX)
SATA_RX: P8.23(PER_P0) P18.27(SATA_RX+)
SATA_RY: P8.25(PER_N0) P18.29(SATA_RX-)
SATA_TX: P8.33(PET_P0) P18.21(SATA_TX+)
SATA_TY: P8.31(PET_N0) P18.23(SATA_TX-)
SBGLD: P13.12(LA) R48.2
SBYLD: P13.9(RA) R49.2
SCL2_I2C_5V: D10.1(CATHODE) J1.15(DDC_CLK) Q2.3(D) R14.1 U20.6(IO4)
SCL_I2C4_3V3: D12.1(CATHODE) P3.4 Q4.3(D) R24.1
SDA2_I2C_5V: D9.1(CATHODE) J1.16(DDC_DATA) Q1.3(D) R12.1 U20.4(IO3)
SDA_I2C4_3V3: D11.1(CATHODE) P3.5 Q3.3(D) R23.1
SDCARD_CLK/JTAG_RTCK/DRM_EMU2: P9.5(CLK) P18.80(SDCARD_CLK) RN3.7(R6) U9.4(IO3)
SDCARD_CMD/JTAG_TDO/UART6_RX/DRM_EMU4: P9.2(CMD) P18.82(SDCARD_CMD) RN3.6(R5) U9.6(IO4)
SDCARD_DATA0/JTAG_TDI/DRM_EMU0: P9.7(DAT0) P18.84(SDCARD_DAT0) RN3.4(R4) U8.6(IO4)
SDCARD_DATA1/JTAG_NTRST/DRM_EMU1: P9.8(DAT1) P18.86(SDCARD_DAT1) RN3.3(R3) U8.4(IO3)
SDCARD_DATA2/JTAG_TMSC/DRM_EMU3: P9.9(DAT2) P18.88(SDCARD_DAT2) RN3.2(R2) U8.3(IO2)
SDCARD_DATA3/JTAG_TCK/DRM_EMU5: P9.1(DAT3) P18.90(SDCARD_DAT3) RN3.1(R1) U8.1(IO1)
SYS_NRESWARM: P18.187(nRESET_WARM) P24.3
TIMER5_PWM_EVT/SDCARD_CD/UART1_CTS/CPI_DATA13/GPIO8_228: P9.11(CD) P18.61(SDCARD_CD) R36.2
TIMER6_PWM_EVT/SDCARD_WP/UART1_RX/CPI_DATA14/GPIO8_229: P9.12(WP) P18.67(SDCARD_WP) R35.2
TIMER8_PWM_EVT/SDCARD_WP/UART1_RTS/CPI_DATA15/GPIO8_230: P18.194(RESERVED5) R9.1 U1.11(MSEN)
TIMER11_PWM_EVT/UART1_TX/CPI_DATA12/GPIO8_227: P18.73(PWM) U3.J6(A14)
TMDS_CLK_LN: J2.12(CK-) L14.2
TMDS_CLK_LP: J2.10(CK+) L14.1
TMDS_TX0_LN: J2.9(D0-) L13.2
TMDS_TX0_LP: J2.7(D0+) L13.1
TMDS_TX1_LN: J2.6(D1-) L12.2
TMDS_TX1_LP: J2.4(D1+) L12.1
TMDS_TX2_LN: J2.3(D2-) L11.2
TMDS_TX2_LP: J2.1(D2+) L11.1
TS_XN: P3.49 P18.68(RTOUCH_X-) P27.3
TS_XP: P3.50 P18.66(RTOUCH_X+) P27.4
TS_YN: P3.48 P18.72(RTOUCH_Y-) P27.2
TS_YP: P3.47 P18.70(RTOUCH_Y+) P27.1
TSC_INT: P3.7 Q10.1(G) R17.1
UART2_CTS/MCSPI3_CS0/USBB1_ULPIPHY_DATA5/GPMC_NOE_NRE/GPIO3_85: P17.6 P18.7(UART2_CTS)
UART2_RTS/MCSPI3_SOMI/USBB1_ULPIPHY_DATA4/GPMC_NWE/GPIO3_84: P17.8 P18.9(UART2_RTS)
UART2_RX/MCSPI3_SIMO/USBB1_ULPIPHY_DATA6/GPMC_NCS5/GPIO3_86: P17.4 P18.5(UART2_RX)
UART2_TX/MCSPI3_CLK/USBB1_ULPIPHY_DATA7/GPMC_NCS6/GPIO3_87: P17.2 P18.3(UART2_TX)
UART3_CTS_RCTX: P12.7 U18.10(B4)
UART3_CTS_RCTX/SATA_ACTLED/USBB2_MM_TXEN/SDIO5_DATA7/USBD0_ULPIPHY_DATA4/GPIO5_153: P18.60 U18.5(A4)
UART3_RTS_IRSD: P12.3 U18.12(B2)
UART3_RTS_IRSD/HDQ_SIO/USBB2_MM_TXDAT/SDIO5_DATA6/USBD0_ULPIPHY_DATA5/GPIO5_154: P18.62 U18.3(A2)
UART3_RX_IRRX: P12.5 U18.11(B3)
UART3_RX_IRRX/SDIO4_CMD/GPIO5_156: P18.147(SDIO_CMD) U18.4(A3)
UART3_TX_IRTX: P12.1 U18.13(B1)
UART3_TX_IRTX/SDIO4_CLK/GPIO5_155: P18.157(SDIO_CLK) U18.2(A1)
UART5_CTS: P12.8 U17.10(B4)
UART5_CTS/SDIO4_DATA0/GPIO5_136: P18.155(SDIO_DAT0) U17.5(A4)
UART5_RTS: P12.4 U17.12(B2)
UART5_RTS/SDIO4_DATA3/GPIO5_137: P18.149(SDIO_DAT3) U17.3(A2)
UART5_RX: P12.6 U17.11(B3)
UART5_RX/SDIO4_DATA1/GPIO5_134: P18.153(SDIO_DAT1) U17.4(A3)
UART5_TX: P12.2 U17.13(B1)
UART5_TX/SDIO4_DATA2/GPIO5_135: P18.151(SDIO_DAT2) U17.2(A1)
USB1N_T: L15.2 P15.2(D-)
USB1P_T: L15.1 P15.3(D+)
USB2N_T: L16.2 P15.6(D-)
USB2P_T: L16.1 P15.7(D+)
USBD0_DM: L17.2 P16.2(D-)
USBD0_DP: L17.1 P16.3(D+)
USBD0_HS_DM/UART3_TX_IRTX: L17.3 P18.178(HSUSB0_D-)
USBD0_HS_DP/UART3_RX_IRRX: L17.4 P18.176(HSUSB0_D+)
USBD0_ID/PMIC_GPIO0: P16.4(ID) P18.174(USBOTG_ID)
USBD0_RX: L19.1 P16.10(RX+)
USBD0_RY: L19.2 P16.9(RX-)
USBD0_SS_RX: L19.4 P18.182(SSUSB_RX+)
USBD0_SS_RY: L19.3 P18.184(SSUSB_RX-)
USBD0_SS_TX: C155.1 P18.188(SSUSB_TX+)
USBD0_SS_TY: C154.1 P18.190(SSUSB_TX-)
USBD0_TX: L18.1 P16.7(TX+)
USBD0_TY: L18.2 P16.6(TX-)
USBD0TX: C155.2 L18.4
USBD0TY: C154.2 L18.3
USBH_DM1: L15.3 P18.170(HSUSB1_D-)
USBH_DM2: L16.3 P18.164(HSUSB2_D-)
USBH_DM3: P18.158(HSUSB3_D-) P26.2(D-)
USBH_DP1: L15.4 P18.172(HSUSB1_D+)
USBH_DP2: L16.4 P18.166(HSUSB2_D+)
USBH_DP3: P18.160(HSUSB3_D+) P26.3(D+)
VAC_BRCK_IN: D8.CATHODE FB7.1 J8.1(CENTRAL)
VAC_DETECT: P18.181(RESERVED3) R80.1 R108.1
VREF: R96.2 R97.1 U1.3(VREF)
VSYNC: P3.16 U3.G2(B11)
WLD_CAT: P3.2 R26.1 R28.1
WLD_OUT: D2.1(CATHODE) D3.1(CATHODE) P3.1
WLD_RES: R27.1 R28.2
WLD_SW: D2.2(ANODE) L5.2 U4.1(SW)
YLED: DS3.ANODE R62.1
N16777602: D5.3(CATHODE) P13.10(RK)
N16798094: FB6.2 P16.1(5VUSB)
N16825747: P18.119(PCIE_REFCLK+) TP3.1
N16912917: R89.2 R90.2 R91.1 R92.1
N17036209: R95.2 U1.49(N~{C}AVDD)
N17045594: J1.19(HP_DET) U20.1(IO1)

Not connected (* = marked no-connect by the designer): J1 13(CE_Remote)* 14(NC)*; J2 14(NC)*; J6 3(R)*; P3 8*; P7 23*; P8 1(WAKE#)* 3(RSVD1)* 5(RSVD2)* 6(+1.5V_1)* 7(CLKREQ#)* 8(RSVD13)* 10(RSVD14)* 11(REFCLK-)* 12(RSVD15)* 13(REFCLK+)* 14(RSVD16)* 16(RSVD17)* 17(RSVD3)* 19(RSVD4)* 20(RSVD18)* 22(PERST#)* 28(+1.5V_2)* 30(SMB_CLK)* 32(SMB_DATA)* 36(USB_D-)* 38(USB_D+)* 42(LED_WWAN#)* 43(RSVD8)* 44(LED_WLAN#)* 45(RSVD9)* 46(LED_WPAN#)* 47(RSVD10)* 48(+1.5V_3)* 49(RSVD11)* 51(RSVD12)*; P11 2* 4* 7*; P18 11(UART1_TX)* 13(UART1_RX)* 15(UART1_CTS)* 17(UART1_RTS)* 18(MDI2-)* 20(MDI2+)* 24(MDI3-)* 26(MDI3+)* 54* 56*; RN1 6(RC2); RN2 2(RB1); RN3 8(R7)* 9(R8)*; RN4 3(RC1) 4(RD1) 5(RD2) 6(RC2); SW3 1 4; U2 A2(NC)* A3(NC)* A4(NC)* A5(NC)* K2(NC)* K3(NC)* K4(NC)* K5(NC)*; U3 A2(NC)* A3(NC)* A4(NC)* A5(NC)* F1(B8) F6(A8) H2(B13)* H5(A13)* J2(B15)* J5(A15)* K2(NC)* K3(NC)* K4(NC)* K5(NC)*; U6 5(VBUS)*; U9 1(IO1)* 3(IO2)*; U11 3(FLG_B)* 4(EN_B)* 5(OUT_B)*; U15 24(NC); U17 6(NC)* 9(NC)*; U18 6(NC)* 9(NC)*; U20 5(VBUS)*

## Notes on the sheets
sheet 1
- SB-T54
- BOARD REVISION: 1.0
- PAGE
- FUNCTION
- 01
- INDEX & BLOCK DIAGRAM
- 02
- CARRIER BOARD INTERFACE
- 03
- DVI Transmitter
- 04
- Parallel RGB
- 05
- VIDEO\SATA\EEPROM
- 06
- MMC & UARTS
- 07
- ETH\USB\AUDIO
- 08
- SETUP
- 09
- POWER
- 10
- INFO
sheet 2
- 1-WIRE
- hdq_sio
- MUXED
- DISPLAY
  Parallel
  RGB
- dispc_data17
  dispc_data16
  dispc_pclk
  dispc_de
  dispc_data8
  dispc_data9
  dispc_data10
  dispc_data11
  dispc_data12
  dispc_data13
  dispc_data14
  dispc_data15
  dispc_data18
  dispc_data19
  dispc_data20
  dispc_data21
  dispc_data22
  dispc_data23
  dispc_data0
  dispc_data1
  dispc_data2
  dispc_data3
  dispc_data4
  dispc_data5
  dispc_data6
  dispc_data7
  dispc_hsync
  dispc_vsync
  dispc_fid
- MUXED
  MUXED
  MUXED
  MUXED
  MUXED
  MUXED
  MUXED
  MUXED
  MUXED
  MUXED
  MUXED
  MUXED
  MUXED
  MUXED
  MUXED
  MUXED
  MUXED
  MUXED
  MUXED
  MUXED
  MUXED
  MUXED
  MUXED
  MUXED
  MUXED
  MUXED
  MUXED
  MUXED
  MUXED
- bypass of TOUCH cntrlr
- I2C2
- i2c2_scl
  i2c2_sda
- MUXED
  MUXED
- I2C3
- i2c3_scl
  i2c3_sda
- MUXED
  MUXED
- RESERVED FOR 1Gbps ETHERNET
- I2C4
- i2c4_scl
  i2c4_sda
- MUXED
  MUXED
- RESERVED FOR 1Gbps ETHERNET
- I2C5
- i2c5_scl
  i2c5_sda
- MUXED
  MUXED
- bypass of RS232
  bypass of RS232
- JTAG
- jtag_rtck
  jtag_tdo
  jtag_tdi
  jtag_ntrst
  jtag_tmsc
  jtag_tck
  drm_emu0
  drm_emu1
- MUXED
  MUXED
  MUXED
  MUXED
  MUXED
  MUXED
  MUXED
  MUXED
- DISPLAY
  RFBI
- rfbi_hsync0
  rfbi_te_vsync0
  rfbi_re
  rfbi_a0
  rfbi_data8
  rfbi_data9
  rfbi_data10
  rfbi_data11
  rfbi_data12
  rfbi_data13
  rfbi_data14
  rfbi_data15
  rfbi_data0
  rfbi_data1
  rfbi_data2
  rfbi_data3
  rfbi_data4
  rfbi_data5
  rfbi_data6
  rfbi_data7
  rfbi_cs0
  rfbi_we
- MUXED
  MUXED
  MUXED
  MUXED
  MUXED
  MUXED
  MUXED
  MUXED
  MUXED
  MUXED
  MUXED
  MUXED
  MUXED
  MUXED
  MUXED
  MUXED
  MUXED
  MUXED
  MUXED
  MUXED
  MUXED
  MUXED
- KEYPAD
- kbd_col0
  kbd_col1
  kbd_col2
  kbd_col3
  kbd_col4
  kbd_col5
  kbd_col6
  kbd_col7
  kbd_col8
  kbd_row0
  kbd_row1
  kbd_row2
  kbd_row3
  kbd_row4
  kbd_row5
  kbd_row6
  kbd_row7
  kbd_row8
- MUXED
  MUXED
  MUXED
  MUXED
  MUXED
  MUXED
  MUXED
  MUXED
  MUXED
  MUXED
  MUXED
  MUXED
  MUXED
  MUXED
  MUXED
  MUXED
  MUXED
  MUXED
- DMIC
- abedmic_din1
  abedmic_din2
  abedmic_din3
  abedmic_clk1
  abedmic_clk2
  abedmic_clk3
- MUXED
  MUXED
  MUXED
  MUXED
  MUXED
  MUXED
- bypass of Audio Codec
  bypass of Audio Codec
  bypass of Audio Codec
  bypass of Audio Codec
- DISPLAY
  MIPI-DSI-A
- dsiporta_te0
  dsiporta_lane0x
  dsiporta_lane0y
  dsiporta_lane1x
  dsiporta_lane1y
  dsiporta_lane2x
  dsiporta_lane2y
  dsiporta_lane3x
  dsiporta_lane3y
  dsiporta_lane4x
  dsiporta_lane4y
- MUXED
- bypass of LVDS XCVR
  bypass of LVDS XCVR
  bypass of LVDS XCVR
  bypass of LVDS XCVR
  bypass of LVDS XCVR
  bypass of LVDS XCVR
  bypass of LVDS XCVR
  bypass of LVDS XCVR
  bypass of LVDS XCVR
  bypass of LVDS XCVR
- MCASP
  (incl. SPDIF)
- abemcasp_axr
  abemcasp_ahclkr
  abemcasp_axr
  abemcasp_amutein
  abemcasp_aclkx
  abemcasp_afsr
  abemcasp_aclkr
- MUXED
  MUXED
  MUXED
  MUXED
  MUXED
  MUXED
  MUXED
- bypass of Audio Codec
  bypass of Audio Codec
  bypass of Audio Codec
- MCBSP1
- abemcbsp1_fsx
  abemcbsp1_dx
  abemcbsp1_clkx
  abemcbsp1_dr
- MUXED
  MUXED
  MUXED
  MUXED
- MCBSP3
- abemcbsp3_dr
  abemcbsp3_dx
  abemcbsp3_clkx
  abemcbsp3_fsx
- MUXED
  MUXED
  MUXED
  MUXED
- bypass of Audio Codec
  bypass of Audio Codec
  bypass of Audio Codec
  bypass of Audio Codec
- SLIMBUS
- abeslimbus1_clock
  abeslimbus1_data
- MUXED
  MUXED
- DISPLAY
  HDMI
- hdmi_clkx
  hdmi_clky
  hdmi_data0x
  hdmi_data0y
  hdmi_data1x
  hdmi_data1y
  hdmi_data2x
  hdmi_data2y
  hdmi_cec
  hdmi_ddc_scl
  hdmi_ddc_sda
  hdmi_hpd
- CAMERA
  MIPI-CSI-A
  (data)
- csiporta_lane0x
  csiporta_lane0y
  csiporta_lane1y
  csiporta_lane1x
  csiporta_lane2y
  csiporta_lane2x
  csiporta_lane3x
  csiporta_lane3y
  csiporta_lane4x
  csiporta_lane4y
- MUXED
  MUXED
  MUXED
  MUXED
  MUXED
  MUXED
  MUXED
  MUXED
  MUXED
  MUXED
- MUXED
  MUXED
  MUXED
  MUXED
- SDCARD
- sdcard_clk
  sdcard_cmd
  sdcard_data0
  sdcard_data1
  sdcard_data2
  sdcard_data3
  sdcard_cd
  sdcard_wp
  sdcard_wp
- MUXED
  MUXED
  MUXED
  MUXED
  MUXED
  MUXED
  MUXED
  MUXED
  MUXED
- DNP
- CAMERA
  MIPI-CSI-B
  (data)
- csiportb_lane0x
  csiportb_lane0y
  csiportb_lane1y
  csiportb_lane1x
  csiportb_lane2y
  csiportb_lane2x
- MUXED
  MUXED
  MUXED
  MUXED
  MUXED
  MUXED
- SDIO4
- sdio4_data1
  sdio4_data2
  sdio4_data0
  sdio4_data3
  sdio4_clk
  sdio4_cmd
- MUXED
  MUXED
  MUXED
  MUXED
  MUXED
  MUXED
- CAMERA
  MIPI-CSI-C
  (data)
- csiportc_lane0y
  csiportc_lane0x
  csiportc_lane1y
  csiportc_lane1x
- MUXED
  MUXED
  MUXED
  MUXED
- SPI4
- mcspi4_clk
  mcspi4_simo
  mcspi4_somi
  mcspi4_cs0
- MUXED
  MUXED
  MUXED
  MUXED
- bypass of WIFI+BT
  bypass of WIFI+BT
  bypass of WIFI+BT
  bypass of WIFI+BT
- UART5
- uart5_rx
  uart5_tx
  uart5_cts
  uart5_rts
- MUXED
  MUXED
  MUXED
  MUXED
- EEPROM WP
- Write Protect
- RS-232
- TXD
  RXD
- CAMERA
  Parallel
  (data)
- cpi_pclk
  cpi_wen
  cpi_data0
  cpi_data1
  cpi_data2
  cpi_data3
  cpi_data4
  cpi_data5
  cpi_data6
  cpi_data7
  cpi_data12
  cpi_data13
  cpi_data14
  cpi_data15
  cpi_hsyncin
  cpi_vsyncin
  cpi_data8
  cpi_data9
  cpi_data10
  cpi_data11
  cpi_fid
  cpi_data12
  cpi_data13
  cpi_data14
  cpi_data15
- MUXED
  MUXED
  MUXED
  MUXED
  MUXED
  MUXED
  MUXED
  MUXED
  MUXED
  MUXED
  MUXED
  MUXED
  MUXED
  MUXED
  MUXED
  MUXED
  MUXED
  MUXED
  MUXED
  MUXED
  MUXED
  MUXED
  MUXED
  MUXED
  MUXED
- WLSDIO
- wlsdio_clk
  wlsdio_cmd
  wlsdio_data0
  wlsdio_data1
  wlsdio_data2
  wlsdio_data3
- MUXED
  MUXED
  MUXED
  MUXED
  MUXED
  MUXED
- bypass of WIFI+BT
  bypass of WIFI+BT
  bypass of WIFI+BT
  bypass of WIFI+BT
  bypass of WIFI+BT
  bypass of WIFI+BT
- UART1
- uart1_tx
  uart1_cts
  uart1_rx
  uart1_rts
- MUXED
  MUXED
  MUXED
  MUXED
- USB SS+HS
  OTG
- usbd0_hs_dp
  usbd0_hs_dm
  usbd0_ss_tx
  usbd0_ss_ty
  usbd0_ss_rx
  usbd0_ss_ry
  VBUS_5V_OTG
  USB0_ID
- MUXED
  MUXED
- TIMERS
  PWM
- timer11_pwm_evt
  timer5_pwm_evt
  timer6_pwm_evt
  timer8_pwm_evt
- MUXED
  MUXED
  MUXED
  MUXED
- POWER /
  CHARGER /
  SYSTEM CONTROL
- COLD_RESET_IN
  PWRON
  REGEN1
  ENABLE1
  NRESWARM
  VBAT_SENSE
  VAC_DETECT
  PMID
  GPADC_VREF
  GPADC_IN2
  GPADC_IN1
  GPADC_IN0
  BACKUP_BAT
  USB_PSEL
  VCC_EMMCSDIO_3V3
  ALT_BOOT
- SPI1
- mcspi1_clk
  mcspi1_somi
  mcspi1_simo
  mcspi1_cs0
  mcspi1_cs1
- MUXED
  MUXED
  MUXED
  MUXED
  MUXED
- UART2
- uart2_rts
  uart2_cts
  uart2_rx
  uart2_tx
- MUXED
  MUXED
  MUXED
  MUXED
- 100Mbps LAN
- LED1
  LED2
  LED3
  VDDA
  RXP
  TXP
  RXN
  TXN
- General
  Purpose
  Clock OUT
- fref_clk0_out
- MUXED
- bypass of Audio Codec
- SPI2
- mcspi2_cs1
  mcspi2_cs0
  mcspi2_clk
  mcspi2_simo
  mcspi2_somi
- MUXED
  MUXED
  MUXED
  MUXED
  MUXED
- bypass of TOUCH cntrlr
  bypass of TOUCH cntrlr
  bypass of TOUCH cntrlr
  bypass of TOUCH cntrlr
- UART3
- uart3_rx_irrx
  uart3_tx_irtx
  uart3_cts_rctx
  uart3_rts_irsd
  uart3_tx_irtx
  uart3_rx_irrx
  uart3_rx_irrx
  uart3_tx_irtx
- MUXED
  MUXED
  MUXED
  MUXED
  MUXED
  MUXED
  MUXED
  MUXED
- Analog audio
- RLINEIN
  RHPOUT
  LLINEIN
  LHPOUT
  MICBIAS
  MICIN
- LVDS 0
- TXP0
  TXN0
  TXP1
  TXN1
  TXP2
  TXN2
  TXP3
  TXN3
  CLKP
  CLKN
- SPI3
- mcspi3_somi
  mcspi3_cs0
  mcspi3_simo
  mcspi3_clk
- MUXED
  MUXED
  MUXED
  MUXED
- CAMERA
  discrete
  controls
- cam_shutter
  cam_strobe
  cam_globalreset
  cam_shutter
- MUXED
  MUXED
  MUXED
  MUXED
- UART4
- uart4_rx
  uart4_tx
- MUXED
  MUXED
- bypass of RS232
  bypass of RS232
- SATA
- sata_tx
  sata_ty
  sata_rx
  sata_ry
  sata_actled
- MUXED
sheet 3
- DVI HARDWARE CONFIGURATION
- DVI TRANSMITTER
- OUTPUT SWING
  ADJUST
- VREF ADJUST
- ASSEMBLY OPTIONS:
  THIS CONTROLS
  THE OUTPUT SIGNAL SWING
  AND SHOULD BE
  SET TO 510 OHMS
  NOTE: see datasheet for
  more information
- B0
- B1
- B2
- B3
- ADJUSTS INPUTSIGNALS VOLTAGE 1.8V
- B4
- B5
- B6
- B7
- G0
- G1
- G2
- CLOCK EDGE
  STRAP/ HOT PLUG
  DETECT
- G3
- G4
- G5
- G6
- INPUT MODE
  SELECT/I2C
  CLOCK
- IF I2C DISABLED:
  1 = RISING EDGE CLOCK
  0 = FALLING EDGE CLOCK
- G7
- R0
- R1
- R2
- R3
- IF I2C ENABLED
  THIS SIGNAL IS USED
  FOR HOT PLUG DETECTION
- R4
- IF I2C ENABLED
  THIS SIGNAL
  IS USED
  AS I2C CLOCK
- R5
- R6
- R7
- DE
- VSYNC
- IF I2C DISABLED:
  1 = INPUT IS 24
  BIT SINGLE EGDE
  0 = INPUT IS 12
  BIT DUAL EGDE
- DESKEW STRAPS
- HSYNC
- IF I2C IS DISABLED
  & DESKEW ENABLED:
  USED TO ADJUST THE SETUP &
  HOLD TIMES OF THE PIXEL
  DATA WITH PIXELCLOCK
  NOTE: see datasheet for more
  information
- DVI_PH
- CLOCK MODE
  SELECT/I2C
  DATA
- IF I2C IS DISABLED
  & DESKEW DISABLED:
  THESE ARE THREE
  ADDITIONAL CONTROL INPUTS
  (FOR HDCP & MORE)
- IF I2C
  ENABLED
  THIS SIGNAL
  IS USED
  AS I2C DATA
- IF I2C IS ENABLED
  THOSE CONTROL I2C
  ADDRESS LSB
- IF I2C DISABLED:
  DETERMINES WITH VREF PIN
  THE PIXEL CLOCK INPUT
  (DIFFERENTIAL OR SINGLE-ENDED)
  NOTE: see datasheet
  for more information
- I2C 5V
- DESKEW ENABLE
  STRAP
- IF I2C IS DISABLED
  & DESKEW ENABLED:
  1 = DESKEW (DEFINED
  BY DESKEWSTRAPS) ENABLED
  0 = DESKEW (DEFINED
  BY DESKEW STRAPS) DISABLED
- ASSEMBLY OPTIONS:
  1 = I2C  ENABLED
  0 = I2C  DISABLED
- DNP
- DNP
- DVI
- DNP
sheet 4
- 24bit Parallel RGB LCD
- B0
- B1
- B2
- B3
- B4
- B5
- B6
- B7
- G0
- TSC_INT
- G1
- touch screen interrupt
- G2
- G3
- G4
- G5
- G6
- G7
- R0
- R1
- R2
- R3
- R4
- R5
- R6
- R7
- DE
- VSYNC
- RST_DISP
- HSYNC
- I2C4 3.3V
- Typical LED configuration 6 serially connected LED's
- 3.6V typical Vf x 6 = 21.6V 15-20mA
- DNP
- DNP
sheet 5
- MMC\SD CARD (boot)
- RS232 MAIN
- RS232
- DNP
- UARTs
- UART3
- UART5
sheet 6
- Valid Boot Configurations
- ALT_BOOT
- SYS_BOOT[3:0]
- 1st device
- 2nd device
- 3rd device
- Released (logic 0)
- 1000
- eMMC
- USB
- N/A
- Pressed (logic 1)
- 1011
- SATA
- SDCARD
- USB
- POWER
  ON\OFF
- RESET
- Boot Select
- I2C\CONTROL\GPIO
- only input GPIO
- UART\SPI\ADC
- WRITE PROTECTION:
  CoM EEPROM
  CLOSE => writeable
  OPEN   => write protected
- CAMERAS
sheet 7
- +V5A  POWER SOURCE 10A
- 3.3V UP TO 3A
- DNP
- POWER SUPPLY
- 1.8V UP TO 3A
- DNP
- 12V INPUT
- DNP
- BACKUP BATTERY
- DNP
- Alignment
  plastic
  pin
- DNP
- DNP
sheet 8
- AUDIO
- ETHERNET
- AUDIO OUT
- G=50k/(Rmic+10k)
- LINE IN
- MIC.IN
- USB OTG
- USB
- USB 3
- USB 1
- USB 2
sheet 9
- LVDS 0
- SATA
- DNP
- SB INFO
  EEPROM
- DNP
- DNP
- I2C4: 50h
- HDMI CM
- DNP
- DNP
- DNP
